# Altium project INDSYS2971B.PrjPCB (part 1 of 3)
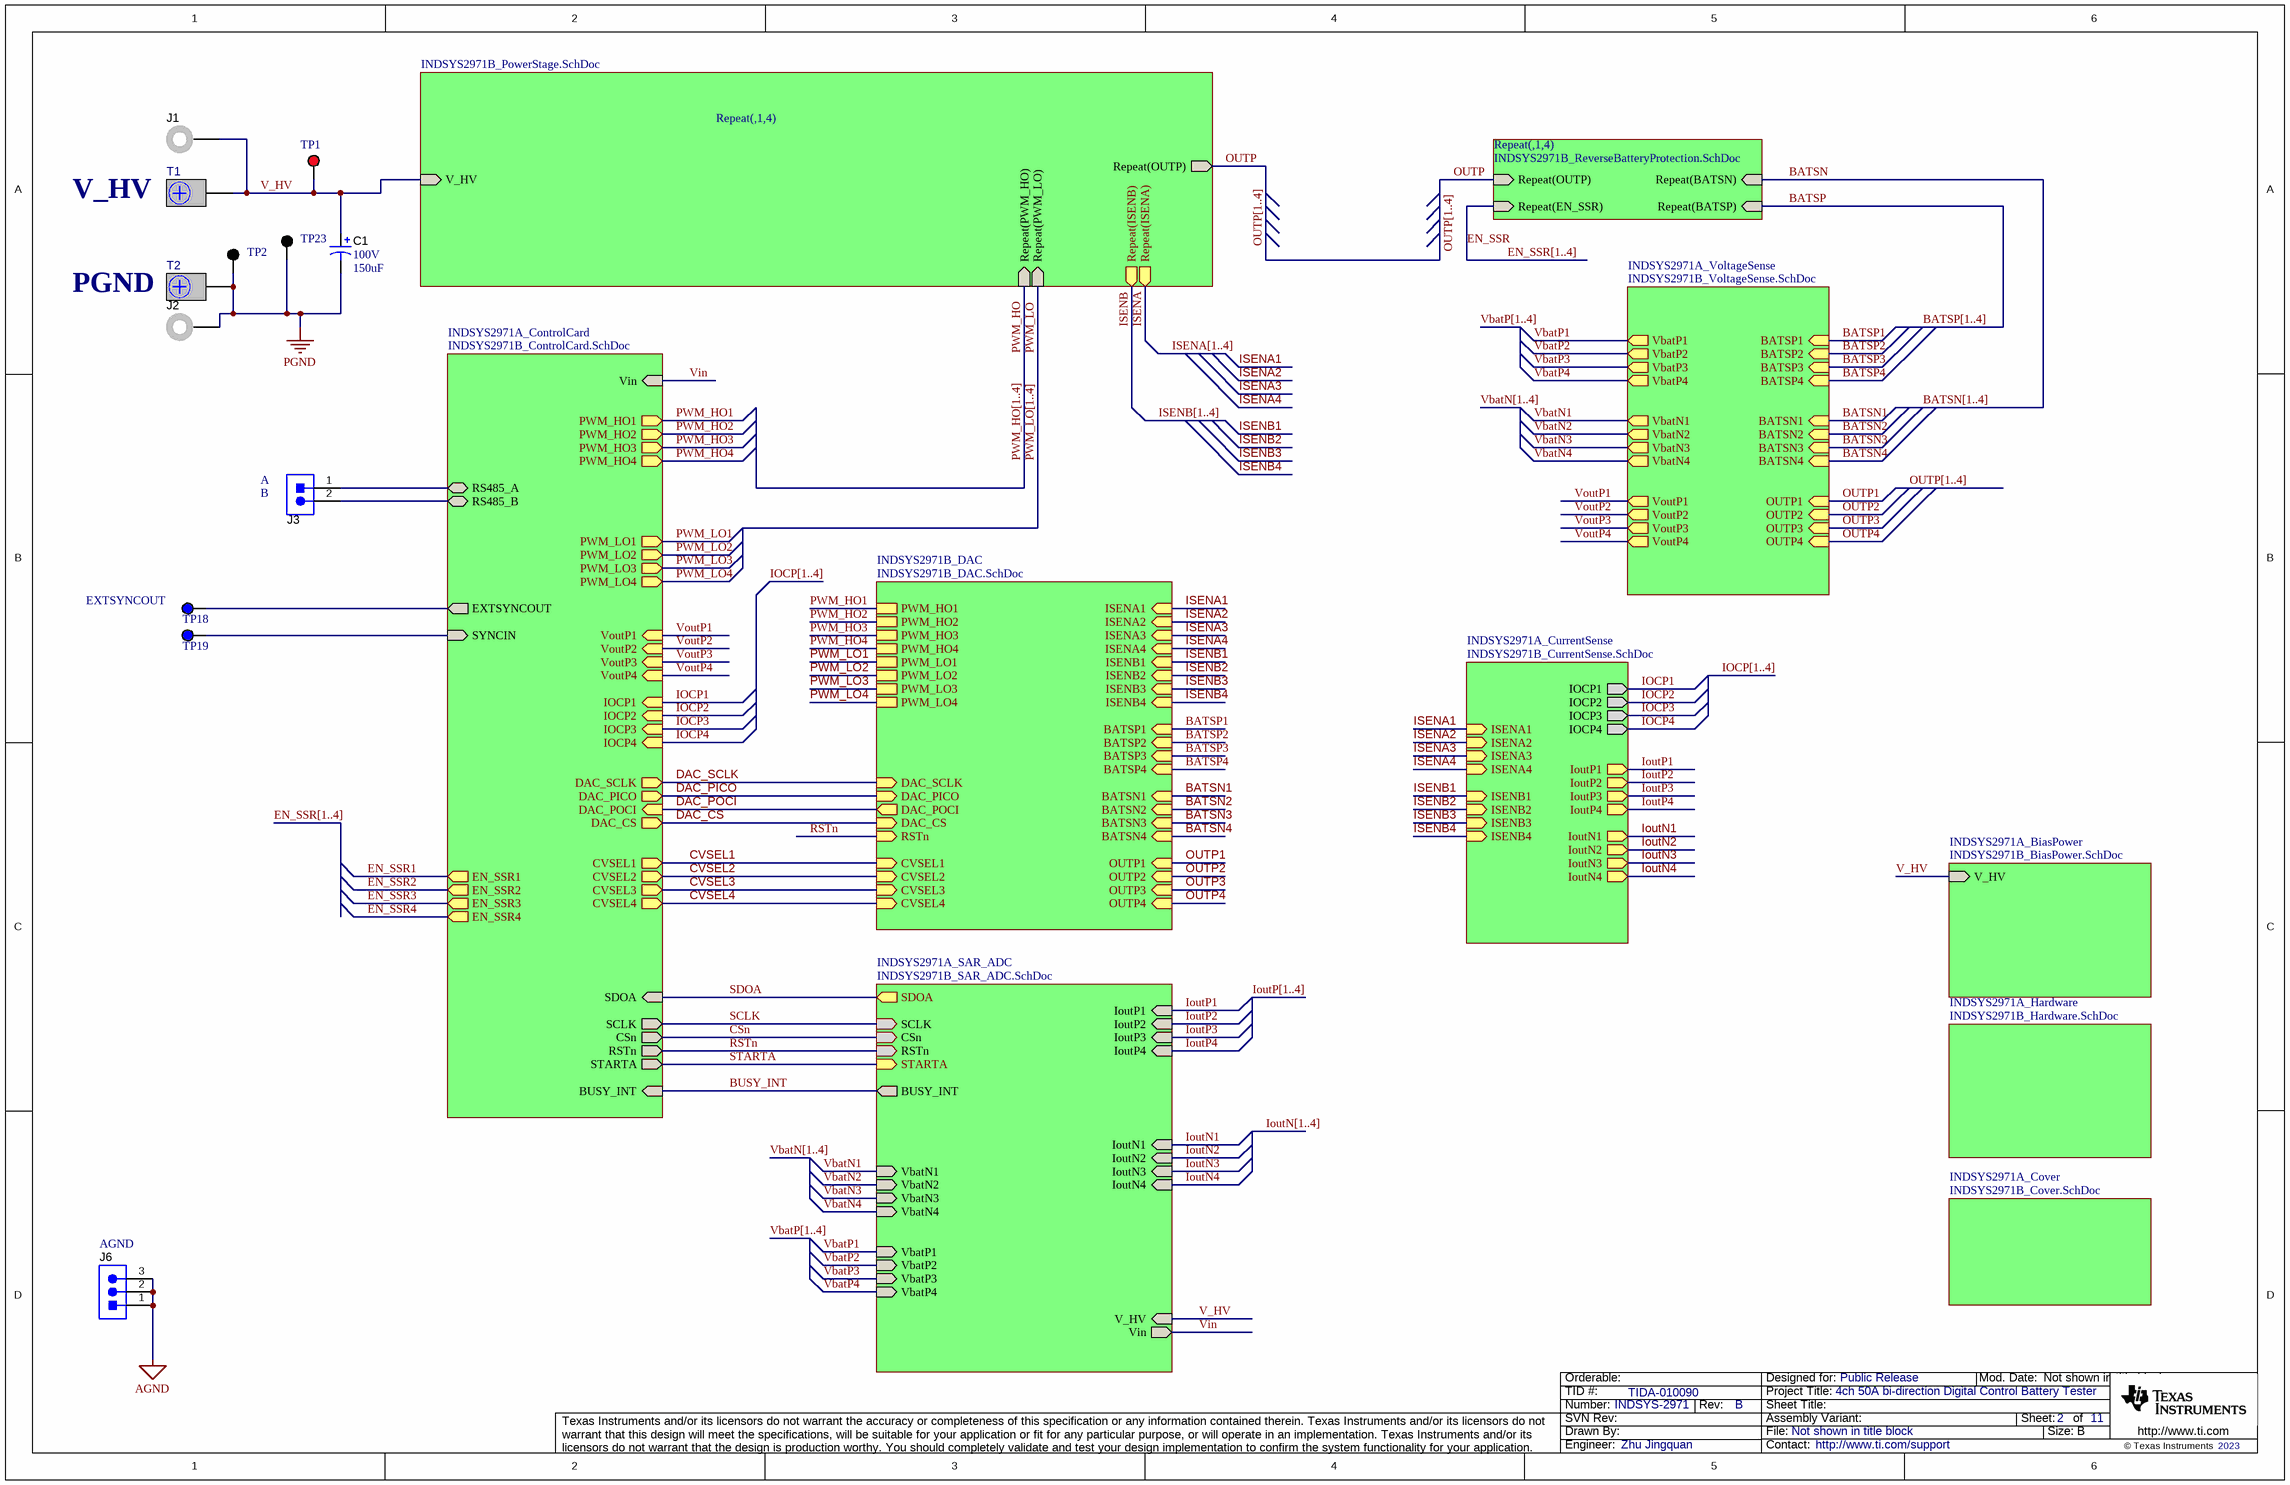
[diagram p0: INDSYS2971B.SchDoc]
CopyrightYear: 2023; PCB_Layout: Zhu Jingquan; PCB_Rev: B; PRJ_Customer: Public Release; PRJ_Engineer: Zhu Jingquan; PRJ_Number: INDSYS-2971; PRJ_Title: 4ch 50A bi-direction Digital Control Battery Tester; SCH_Rev: B; TechSupport: http://www.ti.com/support; TID: TIDA-010090
11 sheets, 788 parts. Net scope: hierarchical (ports join the sheet entries above them; power ports are global).
Board file: INDSYS2971B.PcbDoc
Sheets:
  INDSYS2971B.SchDoc
    1 = INDSYS2971B_PowerStage.SchDoc
    2 = INDSYS2971B_PowerStage.SchDoc
    3 = INDSYS2971B_PowerStage.SchDoc
    4 = INDSYS2971B_PowerStage.SchDoc
    1 = INDSYS2971B_ReverseBatteryProtection.SchDoc
    2 = INDSYS2971B_ReverseBatteryProtection.SchDoc
    3 = INDSYS2971B_ReverseBatteryProtection.SchDoc
    4 = INDSYS2971B_ReverseBatteryProtection.SchDoc
    INDSYS2971A_SAR_ADC = INDSYS2971B_SAR_ADC.SchDoc
    INDSYS2971A_BiasPower = INDSYS2971B_BiasPower.SchDoc
    INDSYS2971A_ControlCard = INDSYS2971B_ControlCard.SchDoc
    INDSYS2971A_Hardware = INDSYS2971B_Hardware.SchDoc
    INDSYS2971A_Cover = INDSYS2971B_Cover.SchDoc
    INDSYS2971A_CurrentSense = INDSYS2971B_CurrentSense.SchDoc
    INDSYS2971A_VoltageSense = INDSYS2971B_VoltageSense.SchDoc
    INDSYS2971B_DAC = INDSYS2971B_DAC.SchDoc

## Sheet INDSYS2971B.SchDoc
size 431 x 279 mm; Date: Not shown in title block; ApprovedBy: Not shown in title block; CheckedBy: Not shown in title block; Author: Not shown in title block; CompanyName: Not shown in title block; Engineer: Not shown in title block; Organization: Not shown in title block; Address1: Not shown in title block; Address2: Not shown in title block; Address3: Not shown in title block; Address4: Not shown in title block; DocumentNumber: 2; Revision: Use project parameter SCH_Rev; SheetNumber: 2; SheetTotal: 11; PageSetup: Record=PageOptions¦CenterHorizontal=True¦CenterVertical=True¦PrintScale=1.00¦XCorrection=1.00¦YCorrection=1.00¦PrintKind=0¦BorderSize=5000000¦LeftOffset=0¦BottomOffset=0¦Orientation=2¦PaperLength=1000¦PaperWidth=1000¦Scale=100¦PaperSource=15¦PrintQuality=600¦MediaType=1¦DitherType=10¦PaperKind=Letter¦PrintScaleMode=1

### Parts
C1  VDC_V: 100V  ValueDisplayed: 150uF  [SM_RADIAL_J16]  (hidden comment: EEV-FK2A151M)
J1  108-0740-001  [Johnson_108-0740-001]  (value not drawn)
J2  108-0740-001  [Johnson_108-0740-001]  (value not drawn)
J3  B2B-EH-A(LF)(SN)  [JST_B2B-EH-A]  (value not drawn)
J6  HTSW-103-07-G-S  [Samtec_HTSW-103-07-G-S]  (value not drawn)
T1  CXS70-14-C  [Panduit_CXS70-14-C]  (value not drawn)
T2  CXS70-14-C  [Panduit_CXS70-14-C]  (value not drawn)
TP1  5000  [Keystone5000]  (value not drawn)
TP2  5001  [Keystone5001]  (value not drawn)
TP18  5117  [Keystone5117]  (value not drawn)
TP19  5117  [Keystone5117]  (value not drawn)
TP23  5001  [Keystone5001]  (value not drawn)

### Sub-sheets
INDSYS2971A_BiasPower = INDSYS2971B_BiasPower.SchDoc: V_HV (in)
INDSYS2971A_ControlCard = INDSYS2971B_ControlCard.SchDoc: SDOA (in), SCLK (out), CSn (out), Vin (in), RSTn (out), EXTSYNCOUT (out), SYNCIN (in), BUSY_INT (in), STARTA (out), RS485_A (bidir), RS485_B (bidir), EN_SSR1 (out), EN_SSR2 (out), EN_SSR3 (out), EN_SSR4 (out), IOCP1 (in), IOCP2 (in), IOCP3 (in), IOCP4 (in), VoutP1 (in), VoutP2 (in), VoutP3 (in), VoutP4 (in), PWM_HO1 (out), PWM_HO2 (out), PWM_HO3 (out), PWM_HO4 (out), PWM_LO1 (out), PWM_LO2 (out), PWM_LO3 (out), PWM_LO4 (out), DAC_SCLK (out), DAC_PICO (out), DAC_POCI (in), DAC_CS (out), CVSEL1 (out), CVSEL2 (out), CVSEL3 (out), CVSEL4 (out)
INDSYS2971A_Cover = INDSYS2971B_Cover.SchDoc: no entries
INDSYS2971A_CurrentSense = INDSYS2971B_CurrentSense.SchDoc: IOCP1 (out), IOCP2 (out), IOCP3 (out), IOCP4 (out), IoutP1 (out), IoutP2 (out), IoutP3 (out), IoutP4 (out), IoutN1 (out), IoutN2 (out), IoutN3 (out), IoutN4 (out), ISENA1 (in), ISENA2 (in), ISENA3 (in), ISENA4 (in), ISENB1 (in), ISENB2 (in), ISENB3 (in), ISENB4 (in)
INDSYS2971A_Hardware = INDSYS2971B_Hardware.SchDoc: no entries
INDSYS2971A_SAR_ADC = INDSYS2971B_SAR_ADC.SchDoc: BUSY_INT (out), IoutP1 (in), IoutP2 (in), VbatP1 (in), IoutN4 (in), IoutN1 (in), VbatN1 (in), IoutP3 (in), IoutP4 (in), IoutN3 (in), IoutN2 (in), VbatN2 (in), VbatN3 (in), VbatN4 (in), VbatP2 (in), VbatP3 (in), VbatP4 (in), V_HV (in), Vin (out), SCLK (in), CSn (in), RSTn (in), SDOA (out), STARTA (in)
INDSYS2971A_VoltageSense = INDSYS2971B_VoltageSense.SchDoc: BATSN1 (in), BATSP1 (in), VoutP1 (out), VbatP1 (out), VbatN1 (out), OUTP1 (in), BATSN2 (in), BATSP2 (in), VbatP2 (out), VbatN2 (out), BATSN3 (in), BATSP3 (in), VbatP3 (out), VbatN3 (out), BATSN4 (in), BATSP4 (in), VbatP4 (out), VbatN4 (out), OUTP2 (in), VoutP2 (out), OUTP3 (in), VoutP3 (out), OUTP4 (in), VoutP4 (out)
INDSYS2971B_DAC = INDSYS2971B_DAC.SchDoc: DAC_SCLK (in), DAC_PICO (in), DAC_POCI (out), DAC_CS (in), CVSEL1 (in), CVSEL2 (in), CVSEL3 (in), CVSEL4 (in), RSTn (in), PWM_HO1, PWM_HO2, PWM_HO3, PWM_HO4, PWM_LO1, PWM_LO2, PWM_LO3, PWM_LO4, BATSP1 (in), BATSP2 (in), BATSP3 (in), BATSP4 (in), BATSN1 (in), BATSN2 (in), BATSN3 (in), BATSN4 (in), OUTP1 (in), OUTP2 (in), OUTP3 (in), OUTP4 (in), ISENA1 (in), ISENA2 (in), ISENA3 (in), ISENA4 (in), ISENB1 (in), ISENB2 (in), ISENB3 (in), ISENB4 (in)
Repeat(,1,4) = INDSYS2971B_PowerStage.SchDoc: V_HV (in), Repeat(OUTP) (out), Repeat(PWM_HO) (in), Repeat(PWM_LO) (in), Repeat(ISENB) (out), Repeat(ISENA) (out)
Repeat(,1,4) = INDSYS2971B_ReverseBatteryProtection.SchDoc: Repeat(BATSN) (in), Repeat(BATSP) (in), Repeat(EN_SSR) (in), Repeat(OUTP) (in)

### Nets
AGND: J6.1 J6.2 J6.3
PGND: C1.2(-) J2.1 T2.1 TP2.1 TP23.1
BATSN1: sheet INDSYS2971A_VoltageSense/BATSN1, sheet INDSYS2971B_DAC/BATSN1
BATSN2: sheet INDSYS2971A_VoltageSense/BATSN2, sheet INDSYS2971B_DAC/BATSN2
BATSN3: sheet INDSYS2971A_VoltageSense/BATSN3, sheet INDSYS2971B_DAC/BATSN3
BATSN4: sheet INDSYS2971A_VoltageSense/BATSN4, sheet INDSYS2971B_DAC/BATSN4
BATSP1: sheet INDSYS2971A_VoltageSense/BATSP1, sheet INDSYS2971B_DAC/BATSP1
BATSP2: sheet INDSYS2971A_VoltageSense/BATSP2, sheet INDSYS2971B_DAC/BATSP2
BATSP3: sheet INDSYS2971A_VoltageSense/BATSP3, sheet INDSYS2971B_DAC/BATSP3
BATSP4: sheet INDSYS2971A_VoltageSense/BATSP4, sheet INDSYS2971B_DAC/BATSP4
BUSY_INT: sheet INDSYS2971A_SAR_ADC/BUSY_INT, sheet INDSYS2971A_ControlCard/BUSY_INT
CSn: sheet INDSYS2971A_SAR_ADC/CSn, sheet INDSYS2971A_ControlCard/CSn
CVSEL1: sheet INDSYS2971A_ControlCard/CVSEL1, sheet INDSYS2971B_DAC/CVSEL1
CVSEL2: sheet INDSYS2971A_ControlCard/CVSEL2, sheet INDSYS2971B_DAC/CVSEL2
CVSEL3: sheet INDSYS2971A_ControlCard/CVSEL3, sheet INDSYS2971B_DAC/CVSEL3
CVSEL4: sheet INDSYS2971A_ControlCard/CVSEL4, sheet INDSYS2971B_DAC/CVSEL4
DAC_CS: sheet INDSYS2971A_ControlCard/DAC_CS, sheet INDSYS2971B_DAC/DAC_CS
DAC_PICO: sheet INDSYS2971A_ControlCard/DAC_PICO, sheet INDSYS2971B_DAC/DAC_PICO
DAC_POCI: sheet INDSYS2971A_ControlCard/DAC_POCI, sheet INDSYS2971B_DAC/DAC_POCI
DAC_SCLK: sheet INDSYS2971A_ControlCard/DAC_SCLK, sheet INDSYS2971B_DAC/DAC_SCLK
IOCP1: sheet INDSYS2971A_ControlCard/IOCP1, sheet INDSYS2971A_CurrentSense/IOCP1
IOCP2: sheet INDSYS2971A_ControlCard/IOCP2, sheet INDSYS2971A_CurrentSense/IOCP2
IOCP3: sheet INDSYS2971A_ControlCard/IOCP3, sheet INDSYS2971A_CurrentSense/IOCP3
IOCP4: sheet INDSYS2971A_ControlCard/IOCP4, sheet INDSYS2971A_CurrentSense/IOCP4
IoutN1: sheet INDSYS2971A_SAR_ADC/IoutN1, sheet INDSYS2971A_CurrentSense/IoutN1
IoutN2: sheet INDSYS2971A_SAR_ADC/IoutN2, sheet INDSYS2971A_CurrentSense/IoutN2
IoutN3: sheet INDSYS2971A_SAR_ADC/IoutN3, sheet INDSYS2971A_CurrentSense/IoutN3
IoutN4: sheet INDSYS2971A_SAR_ADC/IoutN4, sheet INDSYS2971A_CurrentSense/IoutN4
IoutP1: sheet INDSYS2971A_SAR_ADC/IoutP1, sheet INDSYS2971A_CurrentSense/IoutP1
IoutP2: sheet INDSYS2971A_SAR_ADC/IoutP2, sheet INDSYS2971A_CurrentSense/IoutP2
IoutP3: sheet INDSYS2971A_SAR_ADC/IoutP3, sheet INDSYS2971A_CurrentSense/IoutP3
IoutP4: sheet INDSYS2971A_SAR_ADC/IoutP4, sheet INDSYS2971A_CurrentSense/IoutP4
ISENA1: sheet INDSYS2971A_CurrentSense/ISENA1, sheet INDSYS2971B_DAC/ISENA1
ISENA2: sheet INDSYS2971A_CurrentSense/ISENA2, sheet INDSYS2971B_DAC/ISENA2
ISENA3: sheet INDSYS2971A_CurrentSense/ISENA3, sheet INDSYS2971B_DAC/ISENA3
ISENA4: sheet INDSYS2971A_CurrentSense/ISENA4, sheet INDSYS2971B_DAC/ISENA4
ISENB1: sheet INDSYS2971A_CurrentSense/ISENB1, sheet INDSYS2971B_DAC/ISENB1
ISENB2: sheet INDSYS2971A_CurrentSense/ISENB2, sheet INDSYS2971B_DAC/ISENB2
ISENB3: sheet INDSYS2971A_CurrentSense/ISENB3, sheet INDSYS2971B_DAC/ISENB3
ISENB4: sheet INDSYS2971A_CurrentSense/ISENB4, sheet INDSYS2971B_DAC/ISENB4
OUTP: sheet Repeat(,1,4)/Repeat(OUTP), sheet Repeat(,1,4)/Repeat(OUTP)
OUTP1: sheet INDSYS2971A_VoltageSense/OUTP1, sheet INDSYS2971B_DAC/OUTP1
OUTP2: sheet INDSYS2971A_VoltageSense/OUTP2, sheet INDSYS2971B_DAC/OUTP2
OUTP3: sheet INDSYS2971A_VoltageSense/OUTP3, sheet INDSYS2971B_DAC/OUTP3
OUTP4: sheet INDSYS2971A_VoltageSense/OUTP4, sheet INDSYS2971B_DAC/OUTP4
PWM_HO1: sheet INDSYS2971A_ControlCard/PWM_HO1, sheet INDSYS2971B_DAC/PWM_HO1
PWM_HO2: sheet INDSYS2971A_ControlCard/PWM_HO2, sheet INDSYS2971B_DAC/PWM_HO2
PWM_HO3: sheet INDSYS2971A_ControlCard/PWM_HO3, sheet INDSYS2971B_DAC/PWM_HO3
PWM_HO4: sheet INDSYS2971A_ControlCard/PWM_HO4, sheet INDSYS2971B_DAC/PWM_HO4
PWM_LO1: sheet INDSYS2971A_ControlCard/PWM_LO1, sheet INDSYS2971B_DAC/PWM_LO1
PWM_LO2: sheet INDSYS2971A_ControlCard/PWM_LO2, sheet INDSYS2971B_DAC/PWM_LO2
PWM_LO3: sheet INDSYS2971A_ControlCard/PWM_LO3, sheet INDSYS2971B_DAC/PWM_LO3
PWM_LO4: sheet INDSYS2971A_ControlCard/PWM_LO4, sheet INDSYS2971B_DAC/PWM_LO4
RSTn: sheet INDSYS2971A_SAR_ADC/RSTn, sheet INDSYS2971A_ControlCard/RSTn, sheet INDSYS2971B_DAC/RSTn
SCLK: sheet INDSYS2971A_SAR_ADC/SCLK, sheet INDSYS2971A_ControlCard/SCLK
SDOA: sheet INDSYS2971A_SAR_ADC/SDOA, sheet INDSYS2971A_ControlCard/SDOA
STARTA: sheet INDSYS2971A_SAR_ADC/STARTA, sheet INDSYS2971A_ControlCard/STARTA
V_HV: C1.1(+) J1.1 T1.1 TP1.1 ; sheet Repeat(,1,4)/V_HV, sheet INDSYS2971A_SAR_ADC/V_HV, sheet INDSYS2971A_BiasPower/V_HV
VbatN1: sheet INDSYS2971A_SAR_ADC/VbatN1, sheet INDSYS2971A_VoltageSense/VbatN1
VbatN2: sheet INDSYS2971A_SAR_ADC/VbatN2, sheet INDSYS2971A_VoltageSense/VbatN2
VbatN3: sheet INDSYS2971A_SAR_ADC/VbatN3, sheet INDSYS2971A_VoltageSense/VbatN3
VbatN4: sheet INDSYS2971A_SAR_ADC/VbatN4, sheet INDSYS2971A_VoltageSense/VbatN4
VbatP1: sheet INDSYS2971A_SAR_ADC/VbatP1, sheet INDSYS2971A_VoltageSense/VbatP1
VbatP2: sheet INDSYS2971A_SAR_ADC/VbatP2, sheet INDSYS2971A_VoltageSense/VbatP2
VbatP3: sheet INDSYS2971A_SAR_ADC/VbatP3, sheet INDSYS2971A_VoltageSense/VbatP3
VbatP4: sheet INDSYS2971A_SAR_ADC/VbatP4, sheet INDSYS2971A_VoltageSense/VbatP4
Vin: sheet INDSYS2971A_SAR_ADC/Vin, sheet INDSYS2971A_ControlCard/Vin
VoutP1: sheet INDSYS2971A_ControlCard/VoutP1, sheet INDSYS2971A_VoltageSense/VoutP1
VoutP2: sheet INDSYS2971A_ControlCard/VoutP2, sheet INDSYS2971A_VoltageSense/VoutP2
VoutP3: sheet INDSYS2971A_ControlCard/VoutP3, sheet INDSYS2971A_VoltageSense/VoutP3
VoutP4: sheet INDSYS2971A_ControlCard/VoutP4, sheet INDSYS2971A_VoltageSense/VoutP4
NetJ3_1: J3.1 ; sheet INDSYS2971A_ControlCard/RS485_A
NetJ3_2: J3.2 ; sheet INDSYS2971A_ControlCard/RS485_B
NetR54_2: TP19.1 ; sheet INDSYS2971A_ControlCard/SYNCIN
NetR71_2: TP18.1 ; sheet INDSYS2971A_ControlCard/EXTSYNCOUT

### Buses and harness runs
bus BATSN[1..4]
bus BATSP[1..4]
bus EN_SSR[1..4]
bus IOCP[1..4]
bus IoutN[1..4]
bus IoutP[1..4]
bus ISENA[1..4]
bus ISENB[1..4]
bus OUTP[1..4]
bus PWM_HO[1..4]
bus PWM_LO[1..4]
bus VbatN[1..4]
bus VbatP[1..4]

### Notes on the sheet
- V_HV
- PGND
- (near J3) A
- (near J3) B
- EXTSYNCOUT
- (near J6) AGND

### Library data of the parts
C1 = CMP-0011222-2: CAP, AL, 150 uF, 100 V, +/- 20%, 0.17 ohm, AEC-Q200 Grade 2, SMD; Manufacturer: Panasonic; TaMin_C: -55°C; ESR_ohm: 0.17; Polarized: Y; SizeAreaWB_mm2: 399; Value: 150uF; TaMax_C: 105°C; SizeZ_mm: 16.5; SizeX_mm: 19; SizeY_mm: 17; Cap_Case: J16; SizeArea_mm2: 323; CompType: Capacitor; Cap_F: 150µF; IRMS_A: 793mA; AEC Grade: 2; AEC Category: Q200; U/M: EA
J1 J2 = CMP-0055387-2: Standard Banana Jack, Uninsulated, 15A; Manufacturer: Cinch Connectivity; CNHeader: FALSE; Green_Lifecycle: Active; Green_REACh: Passed; CT: TRUE
J3 = CMP-0075228-1: Header (Shrouded), 2.5mm, 2x1, Tin, TH; Manufacturer: JST Manufacturing; Pitch_mm: 2.5; Gender: Male; Shrouded: Y; Row_Count: 1; Current_A: 3A; Voltage_V: 250V; CNHeader: False
J6 = CMP-0075484-1: Header, 100mil, 3x1, Gold, TH; Manufacturer: Samtec; Green_REACh: Passed; CT: False; Green_Lifecycle: Active; CNHeader: True
T1 T2 = CMP-0075010-2: Terminal 70A Lug; Manufacturer: Panduit; CompType: Screw Terminal; CNHeader: False; Green_Lifecycle: Not Set; Green_REACh: Incomplete
TP1 = CMP-0055137-2: Test Point, Miniature, Red, TH; Manufacturer: Keystone Electronics; Green_REACh: Passed; Green_Lifecycle: Active; ContactFinish: Silver; CNHeader: FALSE; CT: TRUE
TP2 TP23 = CMP-0055138-2: Test Point, Miniature, Black, TH; Manufacturer: Keystone Electronics; ContactFinish: Silver; Green_Lifecycle: Active; Green_REACh: Passed; CNHeader: FALSE; CT: TRUE
TP18 TP19 = CMP-0055154-1: Test Point, Miniature, Blue, TH; Manufacturer: Keystone; CNHeader: FALSE; Green_Lifecycle: Active; Green_REACh: Passed; ContactFinish: Silver; CT: TRUE

## Sheet INDSYS2971B_PowerStage.SchDoc
size 431 x 279 mm; Date: Not shown in title block; ApprovedBy: Not shown in title block; CheckedBy: Not shown in title block; Author: Not shown in title block; CompanyName: Not shown in title block; DrawnBy: Battery test; Engineer: Not shown in title block; Organization: Not shown in title block; Address1: Not shown in title block; Address2: Not shown in title block; Address3: Not shown in title block; Address4: Not shown in title block; DocumentNumber: 3; Revision: Use project parameter SCH_Rev; SheetNumber: 3; SheetTotal: 11; PageSetup: Record=PageOptions¦CenterHorizontal=True¦CenterVertical=True¦PrintScale=1.00¦XCorrection=1.00¦YCorrection=1.00¦PrintKind=0¦BorderSize=5000000¦LeftOffset=0¦BottomOffset=0¦Orientation=2¦PaperLength=1000¦PaperWidth=1000¦Scale=100¦PaperSource=15¦PrintQuality=600¦MediaType=1¦DitherType=10¦PaperKind=Letter¦PrintScaleMode=1
Used 4 times, as channels 1, 2, 3, 4. Parts and nets are listed once, with the designators drawn on the sheet.
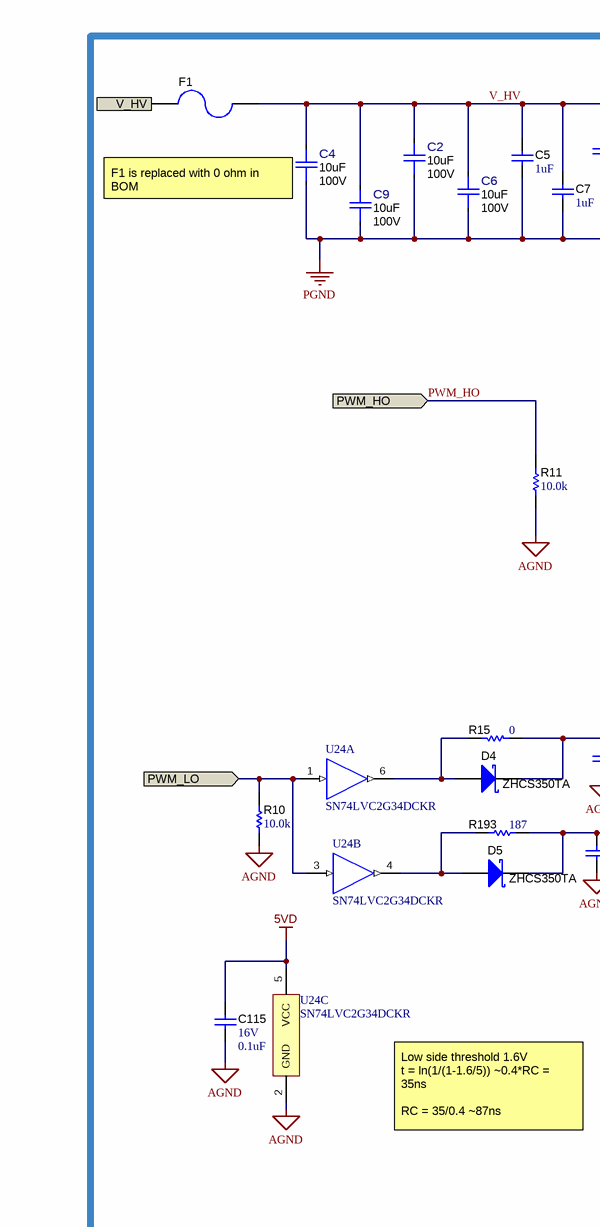
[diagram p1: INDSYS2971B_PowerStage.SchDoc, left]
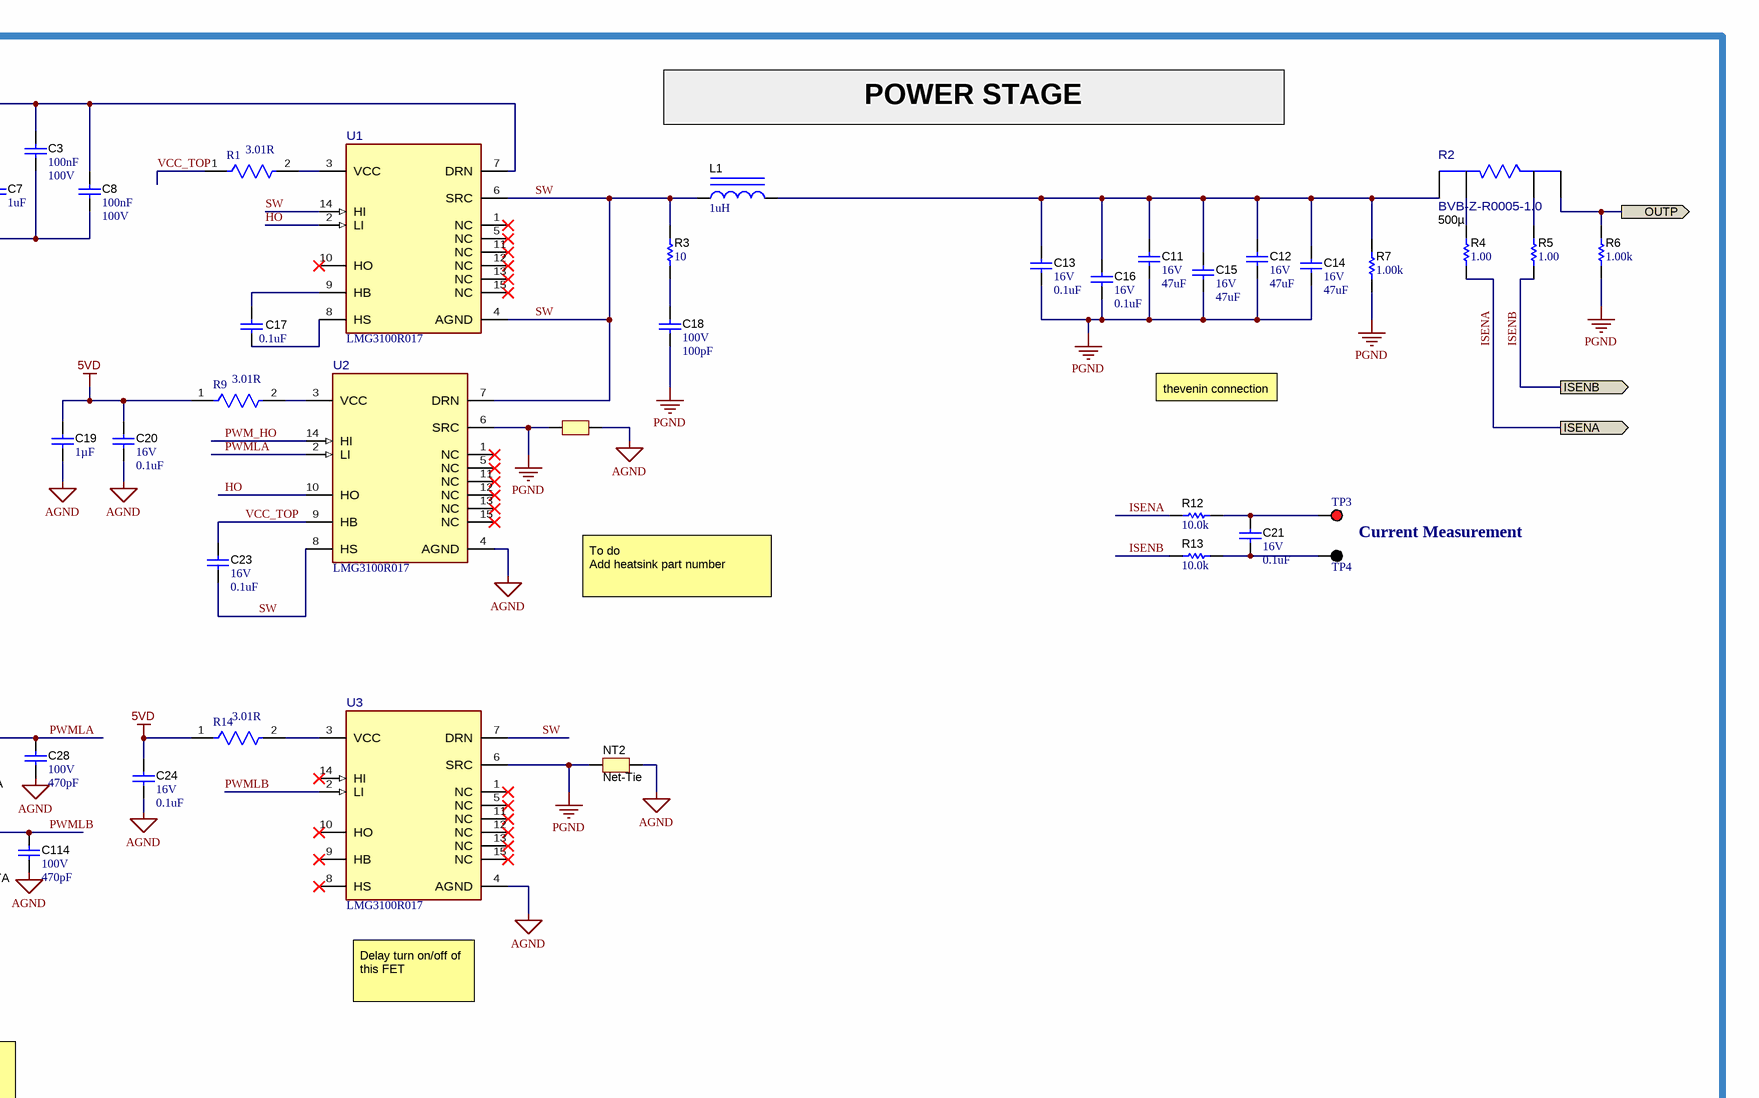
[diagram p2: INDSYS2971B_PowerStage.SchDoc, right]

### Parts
C2  ValueDisplayed: 10uF  VDC_V: 100V  [FP-GRM32EC72A106KE05L_1210-MFG]  (hidden comment: GRM32EC72A106KE05L)
C3  Cap_F: 100nF  VDC_V: 100V  [0603]  (hidden comment: GRM188R72A104KA35D)
C4  ValueDisplayed: 10uF  VDC_V: 100V  [FP-GRM32EC72A106KE05L_1210-MFG]  (hidden comment: GRM32EC72A106KE05L)
C5  ValueDisplayed: 1uF  [0805_HV]  (hidden comment: C2012X7S2A105K125AB)
C6  ValueDisplayed: 10uF  VDC_V: 100V  [FP-GRM32EC72A106KE05L_1210-MFG]  (hidden comment: GRM32EC72A106KE05L)
C7  ValueDisplayed: 1uF  [0805_HV]  (hidden comment: C2012X7S2A105K125AB)
C8  Cap_F: 100nF  VDC_V: 100V  [0603]  (hidden comment: GRM188R72A104KA35D)
C9  ValueDisplayed: 10uF  VDC_V: 100V  [FP-GRM32EC72A106KE05L_1210-MFG]  (hidden comment: GRM32EC72A106KE05L)
C11  VDC_V: 16V  ValueDisplayed: 47uF  [1210_270]  (hidden comment: GRM32EC81C476ME15L)
C12  VDC_V: 16V  ValueDisplayed: 47uF  [1210_270]  (hidden comment: GRM32EC81C476ME15L)
C13  VDC_V: 16V  ValueDisplayed: 0.1uF  [0402]  (hidden comment: GRM155R61C104KA88D)
C14  VDC_V: 16V  ValueDisplayed: 47uF  [1210_270]  (hidden comment: GRM32EC81C476ME15L)
C15  VDC_V: 16V  ValueDisplayed: 47uF  [1210_270]  (hidden comment: GRM32EC81C476ME15L)
C16  VDC_V: 16V  ValueDisplayed: 0.1uF  [0402]  (hidden comment: GRM155R61C104KA88D)
C17  ValueDisplayed: 0.1uF  [0402]  (hidden comment: GRM155R61C104KA88D)
C18  VDC_V: 100V  ValueDisplayed: 100pF  [0805_HV]  (hidden comment: GRM2165C2A101JA01D)
C19  ValueDisplayed: 1µF  [0603S]  (hidden comment: CGA3E1X7R1E105K080AC)
C20  VDC_V: 16V  ValueDisplayed: 0.1uF  [0402]  (hidden comment: GRM155R61C104KA88D)
C21  VDC_V: 16V  ValueDisplayed: 0.1uF  [0402]  (hidden comment: GRM155R61C104KA88D)
C23  VDC_V: 16V  ValueDisplayed: 0.1uF  [0402]  (hidden comment: GRM155R61C104KA88D)
C24  VDC_V: 16V  ValueDisplayed: 0.1uF  [0402]  (hidden comment: GRM155R61C104KA88D)
C28  VDC_V: 100V  ValueDisplayed: 470pF  [0402]  (hidden comment: GRM155R72A471KA01D)
C114  VDC_V: 100V  ValueDisplayed: 470pF  [0402]  (hidden comment: GRM155R72A471KA01D)
C115  VDC_V: 16V  ValueDisplayed: 0.1uF  [0402]  (hidden comment: GRM155R61C104KA88D)
D4  ZHCS350TA  [SOD-523]
D5  ZHCS350TA  [SOD-523]
F1  CB61F15A-TR1  [6125FA]  (value not drawn)
L1  ValueDisplayed: 1uH  [XAL1580]  (hidden comment: XAL1580-102MEB)
NT1  Net-Tie  [Net-Tie_10mil]  (value not drawn)  (net tie, no BOM)
NT2  Net-Tie  [Net-Tie_10mil]  (net tie, no BOM)
R1  Resistance: 3.01R  [FP-CRCW0402-e3-MFG]  (hidden comment: CRCW04023R01FNED)
R2  BVB-Z-R0005-1.0  Res_ohm: 500µ  [FP-WSLP2726L5000FEA_2726-MFG]
R3  ValueDisplayed: 10  [0805_HV]  (hidden comment: CRCW080510R0JNEA)
R4  ValueDisplayed: 1.00  [0402]  (hidden comment: CSR0402FK1R00)
R5  ValueDisplayed: 1.00  [0402]  (hidden comment: CSR0402FK1R00)
R6  ValueDisplayed: 1.00k  [0805_HV]  (hidden comment: CRCW08051K00FKEA)
R7  ValueDisplayed: 1.00k  [0805_HV]  (hidden comment: CRCW08051K00FKEA)
R9  Resistance: 3.01R  [FP-CRCW0402-e3-MFG]  (hidden comment: CRCW04023R01FNED)
R10  ValueDisplayed: 10.0k  [0402]  (hidden comment: PCF0402-12-10K0BT1)
R11  ValueDisplayed: 10.0k  [0402]  (hidden comment: PCF0402-12-10K0BT1)
R12  ValueDisplayed: 10.0k  [0402]  (hidden comment: PCF0402-12-10K0BT1)
R13  ValueDisplayed: 10.0k  [0402]  (hidden comment: PCF0402-12-10K0BT1)
R14  Resistance: 3.01R  [FP-CRCW0402-e3-IPC_C]  (hidden comment: CRCW04023R01FNED)
R15  ValueDisplayed: 0  [0402]  (hidden comment: CRCW04020000Z0ED)
R193  ValueDisplayed: 187  [0402]  (hidden comment: CRCW0402187RFKED)
TP3  5000  [Keystone5000]  (value not drawn)
TP4  5001  [Keystone5001]  (value not drawn)
U1  LMG3100R017  [VBE0015A-MFG]
U2  LMG3100R017  [VBE0015A-MFG]
U3  LMG3100R017  [VBE0015A-MFG]
U24  SN74LVC2G34DCKR  [DCK0006A_N]  (parts A,B,C of 3)

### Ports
ISENA (out), ISENB (out), OUTP (out), PWM_HO (in), PWM_LO (in), V_HV (in)

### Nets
5VD: C19.1 C20.2 C24.2 C115.2 R9.1 R14.1 U24.5(VCC)
AGND: C19.2 C20.1 C24.1 C28.2 C114.2 C115.1 NT1.2 NT2.2 R10.2 R11.2 U2.4(AGND) U3.4(AGND) U24.2(GND)
PGND: C2.1 C3.2 C4.1 C5.2 C6.1 C7.2 C8.2 C9.1 C11.2 C12.2 C13.1 C14.2 C15.2 C16.1 C18.2 NT1.1 NT2.1 R6.1 R7.1 U2.6(SRC) U3.6(SRC)
HO: U1.2(LI) U2.10(HO)
ISENA: R4.1 R12.1 ; port ISENA
ISENB: R5.1 R13.1 ; port ISENB
OUTP: R2.3 R6.2 ; port OUTP
PWM_HO: R11.1 U2.14(HI) ; port PWM_HO
PWM_LO: R10.1 U24.1(1A) U24.3(2A) ; port PWM_LO
PWMLA: C28.1 D4.1(K) R15.2 U2.2(LI)
PWMLB: C114.1 D5.1(K) R193.2 U3.2(LI)
SW: C23.1 L1.1 R3.2 U1.4(AGND) U1.6(SRC) U1.14(HI) U2.7(DRN) U2.8(HS) U3.7(DRN)
V_HV: C2.2 C3.1 C4.2 C5.1 C6.2 C7.1 C8.1 C9.2 F1.1 U1.7(DRN)
V_HV: F1.2 ; port V_HV  [a separate net that carries the same name]
VCC_TOP: C23.2 R1.1 U2.9(HB)
NetC11_1: C11.1 C12.1 C13.2 C14.1 C15.1 C16.2 L1.2 R2.4 R7.2
NetC17_1: C17.1 U1.8(HS)
NetC17_2: C17.2 U1.9(HB)
NetC18_1: C18.1 R3.1
NetC21_1: C21.1 R13.2 TP4.1
NetC21_2: C21.2 R12.2 TP3.1
NetD4_2: D4.2(A) R15.1 U24.6(1Y)
NetD5_2: D5.2(A) R193.1 U24.4(2Y)
NetR1_2: R1.2 U1.3(VCC)
NetR2_1: R2.1 R5.2
NetR2_2: R2.2 R4.2
NetR9_2: R9.2 U2.3(VCC)
NetR14_2: R14.2 U3.3(VCC)

Not connected (* = marked no-connect by the designer): U1 1(NC)* 5(NC)* 10(HO)* 11(NC)* 12(NC)* 13(NC)* 15(NC)*; U2 1(NC)* 5(NC)* 11(NC)* 12(NC)* 13(NC)* 15(NC)*; U3 1(NC)* 5(NC)* 8(HS)* 9(HB)* 10(HO)* 11(NC)* 12(NC)* 13(NC)* 14(HI)* 15(NC)*

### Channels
1: designators end in _1; ports ISENA=ISENA1 ISENB=ISENB1 OUTP=OUTP1 PWM_HO=PWM_HO1 PWM_LO=PWM_LO1 V_HV=V_HV
2: designators end in _2; ports ISENA=ISENA2 ISENB=ISENB2 OUTP=OUTP2 PWM_HO=PWM_HO2 PWM_LO=PWM_LO2 V_HV=V_HV
3: designators end in _3; ports ISENA=ISENA3 ISENB=ISENB3 OUTP=OUTP3 PWM_HO=PWM_HO3 PWM_LO=PWM_LO3 V_HV=V_HV
4: designators end in _4; ports ISENA=ISENA4 ISENB=ISENB4 OUTP=OUTP4 PWM_HO=PWM_HO4 PWM_LO=PWM_LO4 V_HV=V_HV

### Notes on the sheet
- POWER STAGE
- (near C4) F1 is replaced with 0 ohm in BOM
- thevenin connection
- Current Measurement
- To do
  Add heatsink part number
- Delay turn on/off of this FET
- Low side threshold 1.6V
  t = ln(1/(1-1.6/5)) ~0.4*RC = 35ns
  RC = 35/0.4 ~87ns

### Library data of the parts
C2 C4 C6 C9 = CMP-0087970-1: 10µF ±10% 100V Ceramic Capacitor X7S 1210 (3225 Metric); Manufacturer: Murata; Symbol Name: SYM-GRM32EC72A106KE05L; AEC Qualified: No; TempCo: 22%; SizeZ_mm: 2.7mm
C3 C8 = CMP-0007469-4: CAP, CERM, 0.1 uF, 100 V, +/- 10%, X7R, 0603; Manufacturer: MuRata; TaMin_C: -55°C; Polarized: N; SizeAreaWB_mm2: 4.68; Value1: Unknown; U/M: EA; Value: 0.1uF; TaMax_C: 125°C; SizeZ_mm: 1; SizeX_mm: 1.6; SizeY_mm: 0.8; SizeArea_mm2: 1.28; AEC Category: Q200
C5 C7 = CMP-0007891-2: CAP, CERM, 1 uF, 100 V, +/- 10%, X7S, 0805; Manufacturer: TDK; Polarized: N; Value: 1uF; U/M: EA; Cap_F: 1µF; ESR_ohm: 8.255m; Value1: 0.008255 ohm; VDC_V: 100V; IRMS_A: 2.2744A; TaMin_C: -55°C; TaMax_C: 125°C; Cap_Case: 0805; AEC Category: Q200; SizeArea_mm2: 2.5; SizeAreaWB_mm2: 6.75; SizeX_mm: 2; SizeY_mm: 1.25; SizeZ_mm: 1.45
C11 C12 C14 C15 = CMP-0009201-2: CAP, CERM, 47 uF, 16 V, +/- 20%, X6S, 1210; Manufacturer: MuRata; TaMin_C: -55°C; Polarized: N; SizeAreaWB_mm2: 14.7; Value1: Unknown; U/M: EA; Value: 47uF; TaMax_C: 105°C; SizeZ_mm: 2.7; SizeX_mm: 3.2; SizeY_mm: 2.5; Cap_Case: 1210; SizeArea_mm2: 8; Cap_F: 47µF; AEC Category: Q200
C13 C16 C20 C21 C23 C24 C115 = CMP-0006591-2: CAP, CERM, 0.1 uF, 16 V, +/- 10%, X5R, 0402; Manufacturer: MuRata; TaMin_C: -55°C; Polarized: N; SizeAreaWB_mm2: 3; Value1: Unknown; U/M: EA; Value: 0.1uF; TaMax_C: 85°C; SizeZ_mm: 0.6; SizeX_mm: 1; SizeY_mm: 0.5; Cap_F: 100nF; AEC Category: Q200
C17 = CMP-0006591-2: CAP, CERM, 0.1 uF, 16 V, +/- 10%, X5R, 0402; Manufacturer: MuRata; TaMin_C: -55°C; Polarized: N; SizeAreaWB_mm2: 3; Value1: Unknown; U/M: EA; Value: 0.1uF; TaMax_C: 85°C; SizeZ_mm: 0.6; SizeX_mm: 1; SizeY_mm: 0.5; Value2: 16V; Cap_F: 100nF; AEC Category: Q200
C18 = CMP-0008093-2: CAP, CERM, 100 pF, 100 V, +/- 5%, C0G/NP0, 0805; Manufacturer: MuRata; TaMin_C: -55°C; Polarized: N; SizeAreaWB_mm2: 6.75; Value1: Unknown; U/M: EA; Value: 100pF; TaMax_C: 125°C; SizeZ_mm: 1.45; SizeX_mm: 2; SizeY_mm: 1.25; Cap_Case: 0805; SizeArea_mm2: 2.5; AEC Category: Q200
C19 = CMP-0076705-3: CAP, CERM, 1 µF, 25 V,+/- 10%, X7R, AEC-Q200 Grade 1, 0603; Manufacturer: TDK; Polarized: N; Value: 1uF; U/M: EA; VDC_V: 25V; TaMin_C: -55°C; TaMax_C: 125°C; Cap_Case: 1.6x0.8x0.8mm; SizeAreaWB_mm2: 4.68; SizeArea_mm2: 1.28; AEC Qualified: Y; AEC Category: Q200; SizeZ_mm: 1.0; AEC Grade: 1; SizeY_mm: 0.8; SizeX_mm: 1.6
C28 C114 = CMP-0006711-2: CAP, CERM, 470 pF, 100 V, +/- 10%, X7R, 0402; Manufacturer: MuRata; TaMin_C: -55°C; Polarized: N; SizeAreaWB_mm2: 3; Value1: Unknown; U/M: EA; Value: 470pF; TaMax_C: 125°C; SizeZ_mm: 0.6; SizeX_mm: 1; SizeY_mm: 0.5; AEC Category: Q200
D4 D5 = CMP-0028594-3: Diode, Schottky, 40 V, 0.35 A, SOD-523; Manufacturer: Diodes Inc.; SizeY_mm: 0.9; Vf_V: 650mV; Io_A: 350mA; Value2: 0.65V; Green_Lifecycle: Active; AEC Category: Q101; SizeX_mm: 1.7; SizeZ_mm: 0.65; SizeArea_mm2: 1.53; Value1: 0.35A; Green_REACh: Passed; SizeAreaWB_mm2: 5.13; Vr_V: 40V; Value: 40V
F1 = CMP-0003569-2: Fuse, 15 A, SMD; Irating_A: 15A; Rtyp_Ohm: 4m
L1 = CMP-0060973-1: Inductor, Shielded, Composite, 1 uH, 57.5 A, 0.000929 ohm, SMD; Manufacturer: Coilcraft; Isat: 73.5A @ 0.7% inductance drop; Irms: 57.5A @ 40C rise; Green_Lifecycle: Not Set; SizeAreaWB_mm2: 313.04; DCR_ohm: 929µ; Green_REACh: Incomplete; Value: 1uH; Imax_A: 57.5A; SizeZ_mm: 8; SizeX_mm: 15.2; SizeY_mm: 16.2; SizeArea_mm2: 246.24; Ind_H: 1µH; AEC Category: Q200
NT1 NT2 = CMP-0078142-6: Single point connection between nets.
R1 R9 R14 = CMP-02407-004899-1: RES Thick Film, 3.01Ω, 1%, 0.063W, 200ppm/°C, 0402; Max Power Dissipation: 63mW; Voltage Rating (DC): 50V
R2 = CMP-0086415-1: RESISTOR - ISA-WELD SHUNT, 0.000; Manufacturer: Vishay; SizeZ_mm: 3.15mm; Tolerance_%: 1%; Power_W: 9W; TempCo: 75ppm/°C
R3 = CMP-0020448-3: RES, 10, 5%, 0.125 W, AEC-Q200 Grade 0, 0805; Manufacturer: Vishay-Dale; Power_W: 125mW; TempCo: 200 ppm/C; Value_Code: 10R0; Value: 10; EIA_Code: E24; SizeX_mm: 2; SizeY_mm: 1.25; SizeZ_mm: 1.45; Value2: 0.125W; SizeArea_mm2: 2.5; AEC Qualified: Y; VDC_V: 150V; AEC Category: Q200; AEC Grade: 0
R4 R5 = CMP-0081622-1: RES, 1.00, 1%, 0.125 W, 0402; Manufacturer: Stackpole Electronics Inc; Power_W: 125mW; TempCo: 200 ppm/C; Value_Code: 1R00; Value: 1.00; EIA_Code: E96; Res_ohm: 1; SizeY_mm: 0.5; SizeZ_mm: 0.6; Value2: 0.125W; AEC Qualified: N; VDC_V: 200V; AEC Category: Q200; SizeAreaWB_mm2: 3
R6 R7 = CMP-0020951-3: RES, 1.00 k, 1%, 0.125 W, AEC-Q200 Grade 0, 0805; Manufacturer: Vishay-Dale; Power_W: 125mW; TempCo: 100 ppm/C; Value_Code: 1k00; Value: 1.00k; EIA_Code: E96; Res_ohm: 1k; SizeX_mm: 2; SizeY_mm: 1.25; SizeZ_mm: 1.45; Value2: 0.125W; SizeArea_mm2: 2.5; AEC Qualified: Y; VDC_V: 150V; AEC Category: Q200; AEC Grade: 0
R10-R13 = CMP-0026796-1: RES, 10.0 k, 0.1%, 0.063 W, 0402; Manufacturer: TT Electronics/IRC; Power_W: 63mW; TempCo: 10 ppm/C; Value_Code: 10k0; U/M: EA; Value: 10.0k; EIA_Code: E192; Res_ohm: 10k; SizeX_mm: 1; SizeY_mm: 0.5; SizeZ_mm: 0.6; Value2: 0.063W; AEC Qualified: N; VDC_V: 25V; AEC Category: Q200
R15 = CMP-0026822-3: RES, 0, 5%, 0.063 W, AEC-Q200 Grade 0, 0402; Manufacturer: Vishay-Dale; Value: 0; Value_Code: 0000; Power_W: 63mW; Value2: 0.063W; VDC_V: 50V; TempCo: 200 ppm/C; SizeArea_mm2: 0.5; SizeX_mm: 1; SizeZ_mm: 0.6; EIA_Code: E24; AEC Category: Q200; AEC Qualified: Y
R193 = CMP-0026057-3: RES, 187, 1%, 0.063 W, AEC-Q200 Grade 0, 0402; Manufacturer: Vishay-Dale; Power_W: 63mW; TempCo: 100 ppm/C; Value_Code: 187R; Value: 187; EIA_Code: E96; SizeX_mm: 1; SizeY_mm: 0.5; SizeZ_mm: 0.6; Value2: 0.063W; AEC Qualified: Y; VDC_V: 50V; AEC Category: Q200; AEC Grade: 0
TP3 = CMP-0055137-2: as TP1 on sheet INDSYS2971B
TP4 = CMP-0055138-2: as TP2 on sheet INDSYS2971B
U1-U3 = CMP-0037654-1: 100-V, 64-A GaN with Integrated Driver; Manufacturer: Texas Instruments; SizeZ_mm: 0.85mm; AEC Qualified: No; Max Supply Voltage: 5.25V; Min Supply Voltage: 4.75V; Nominal Supply Current: 3mA; Number Of Drivers: 1; Propagation Delay: 55ns; Standoff Height: 0mm; TJmax_C: +125°C
U24 = CMP-0051909-3: Dual Buffer Gate, DCK0006A (SOT-SC70-6); Manufacturer: Texas Instruments; Output Type: CMOS; Bits(#): 2; Input Type: CMOS/TTL; Technology Family: LVC; Schmitt Trigger: No; VCC(Max)(V): 5.5; Rating: Catalog; Output Drive (IOL/IOH)(Max)(mA): 32/-32; ICC @ Nom Voltage(Max)(mA): 0.01; VCC(Min)(V): 1.65; F @ Nom Voltage(Max)(Mhz): 150; Logic: True; Voltage(Nom)(V): 1.8,2.5,3.3,5; tpd @ Nom Voltage(Max)(ns): 8.6,4.4,4.1,3.2; AEC Category: Q200; AEC Qualified: N; CompType: IC; SizeAreaWB_mm2: 9.3; SizeArea_mm2: 4.2; SizeX_mm: 2.1; SizeY_mm: 2.0; SizeZ_mm: 1.1

## Sheet INDSYS2971B_ReverseBatteryProtection.SchDoc
size 431 x 279 mm; Date: Not shown in title block; ApprovedBy: Not shown in title block; CheckedBy: Not shown in title block; Author: Not shown in title block; CompanyName: Not shown in title block; DrawnBy: Battery test; Engineer: Not shown in title block; Organization: Not shown in title block; Address1: Not shown in title block; Address2: Not shown in title block; Address3: Not shown in title block; Address4: Not shown in title block; DocumentNumber: 4; Revision: Use project parameter SCH_Rev; SheetNumber: 4; SheetTotal: 11; PageSetup: Record=PageOptions¦CenterHorizontal=True¦CenterVertical=True¦PrintScale=1.00¦XCorrection=1.00¦YCorrection=1.00¦PrintKind=0¦BorderSize=5000000¦LeftOffset=0¦BottomOffset=0¦Orientation=2¦PaperLength=1000¦PaperWidth=1000¦Scale=100¦PaperSource=15¦PrintQuality=600¦MediaType=1¦DitherType=10¦PaperKind=Letter¦PrintScaleMode=1
Used 4 times, as channels 1, 2, 3, 4. Parts and nets are listed once, with the designators drawn on the sheet.
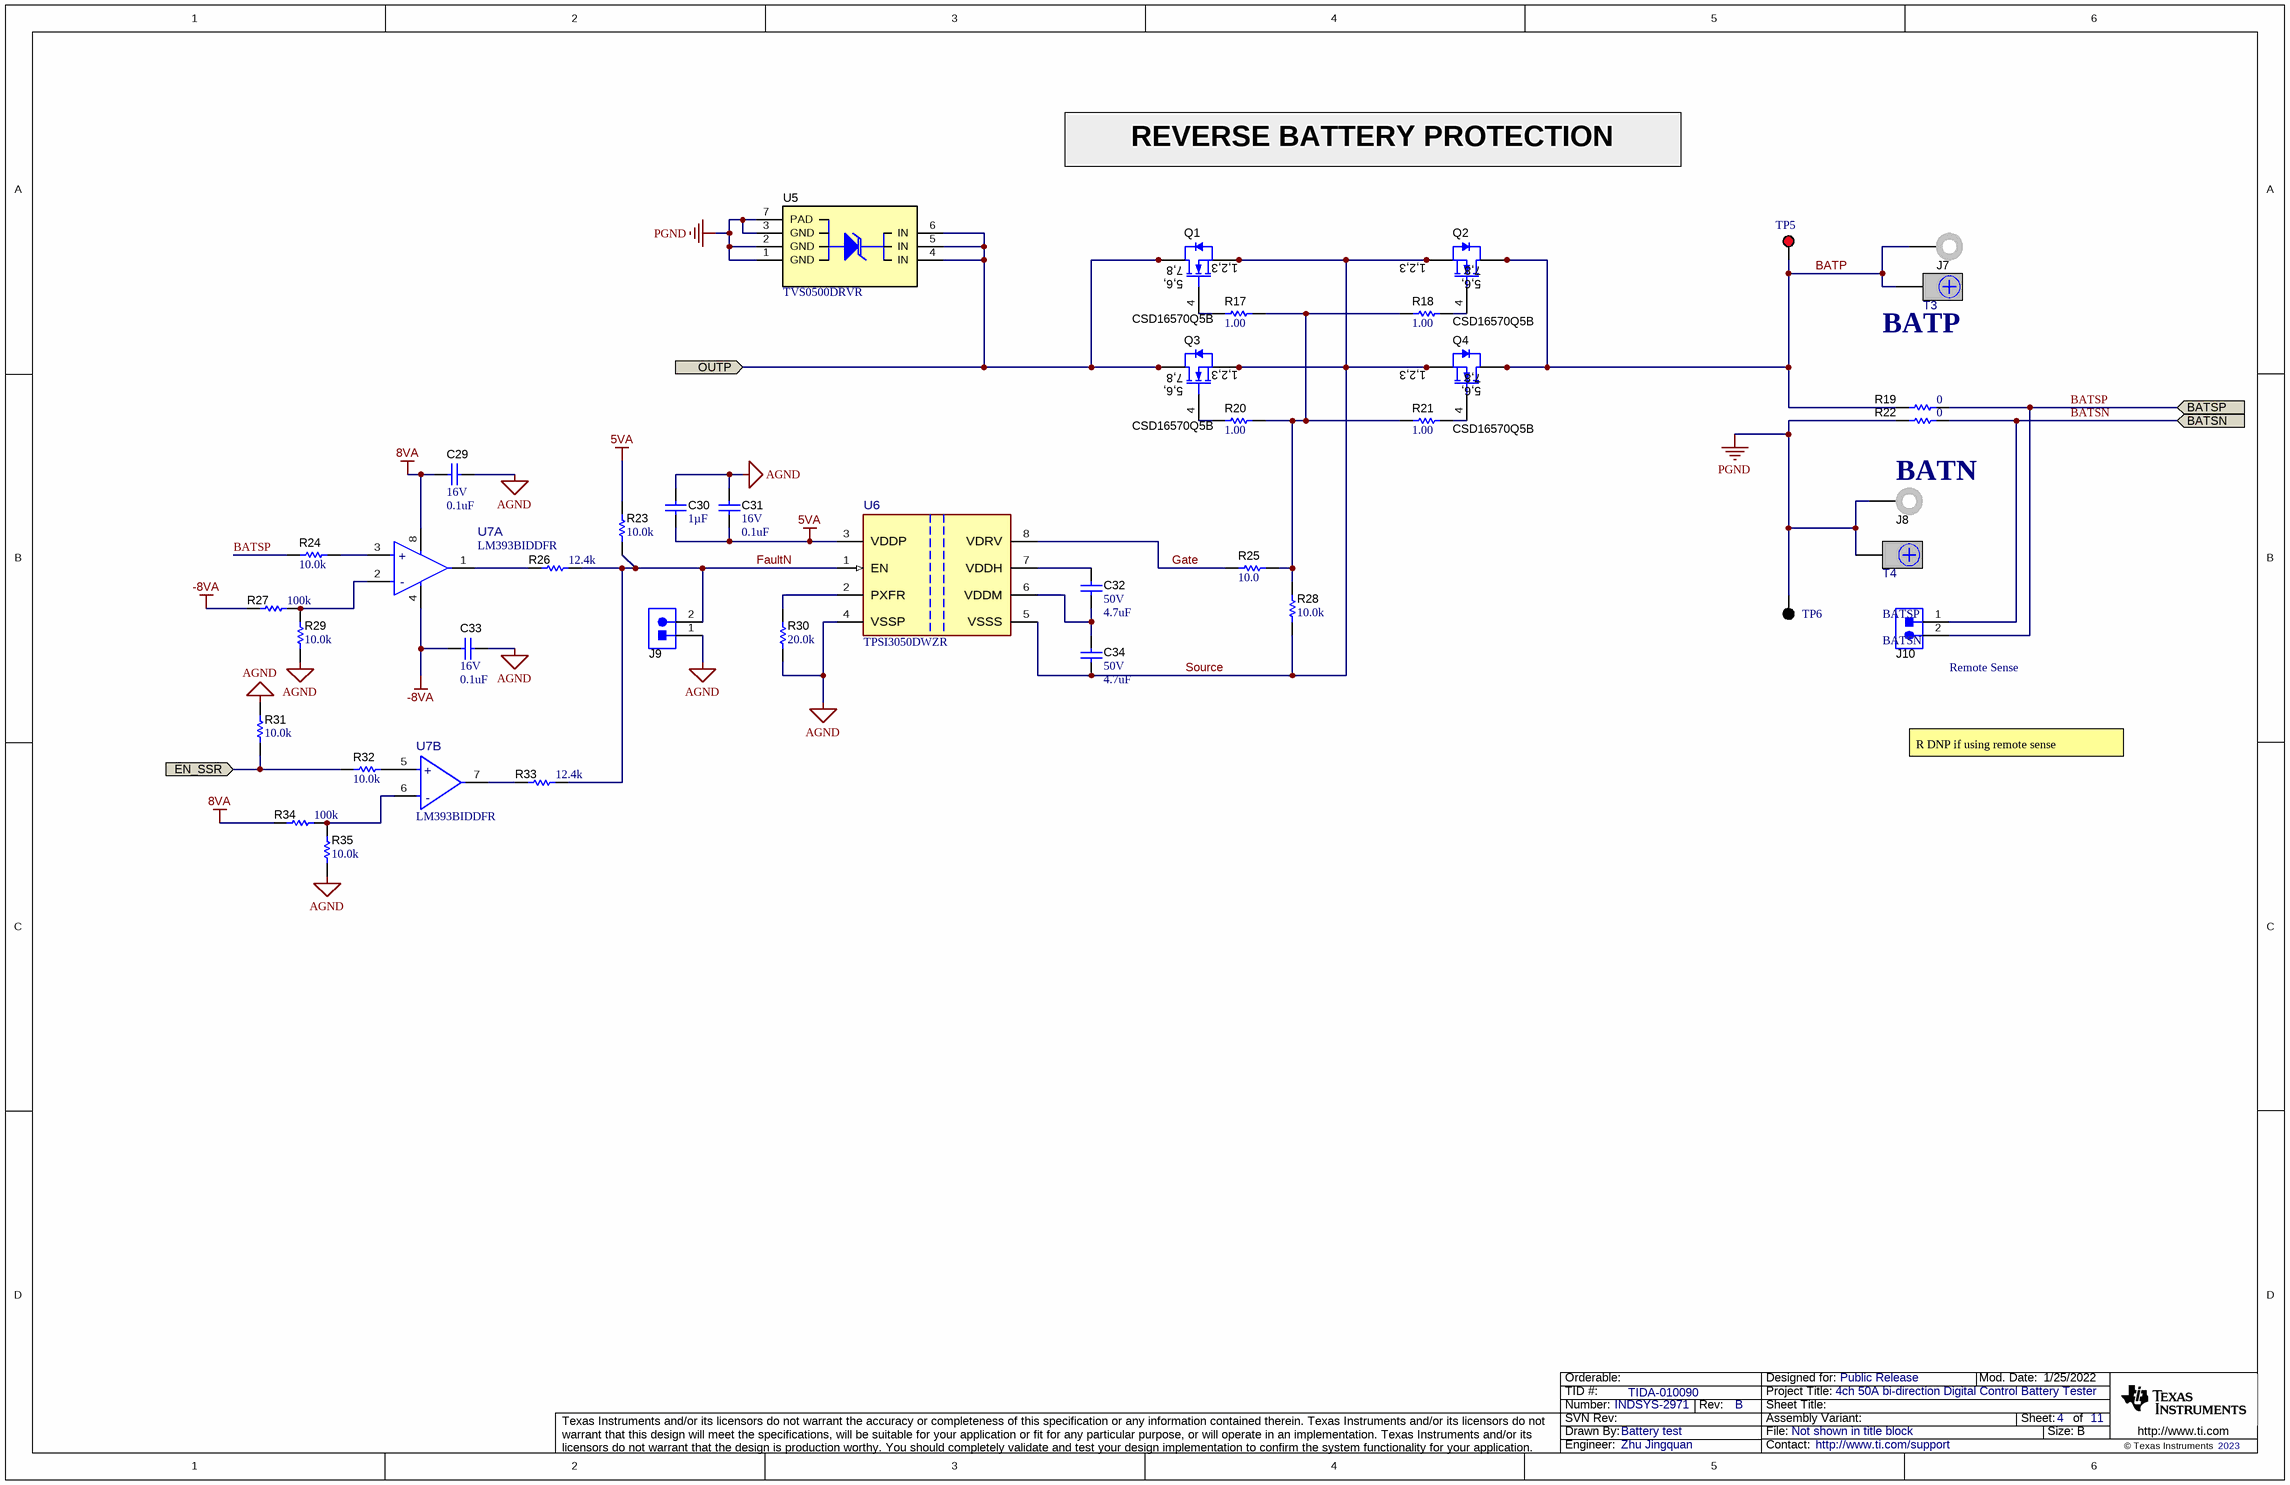
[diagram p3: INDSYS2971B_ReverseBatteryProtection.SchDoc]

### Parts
C29  VDC_V: 16V  ValueDisplayed: 0.1uF  [0402]  (hidden comment: GRM155R61C104KA88D)
C30  ValueDisplayed: 1µF  [0603S]  (hidden comment: CGA3E1X7R1E105K080AC)
C31  VDC_V: 16V  ValueDisplayed: 0.1uF  [0402]  (hidden comment: GRM155R61C104KA88D)
C32  VDC_V: 50V  ValueDisplayed: 4.7uF  [0805_HV]  (hidden comment: GRM21BR61H475KE51L)
C33  VDC_V: 16V  ValueDisplayed: 0.1uF  [0402]  (hidden comment: GRM155R61C104KA88D)
C34  VDC_V: 50V  ValueDisplayed: 4.7uF  [0805_HV]  (hidden comment: GRM21BR61H475KE51L)
J7  108-0740-001  [Johnson_108-0740-001]  (value not drawn)
J8  108-0740-001  [Johnson_108-0740-001]  (value not drawn)
J9  HTSW-102-07-G-S  [Samtec_HTSW-102-07-G-S]  (value not drawn)
J10  B2B-EH-A(LF)(SN)  [JST_B2B-EH-A]  (value not drawn)
Q1  CSD16570Q5B  [DNK0008A]
Q2  CSD16570Q5B  [DNK0008A]
Q3  CSD16570Q5B  [DNK0008A]
Q4  CSD16570Q5B  [DNK0008A]
R17  ValueDisplayed: 1.00  [0402]  (hidden comment: CSR0402FK1R00)
R18  ValueDisplayed: 1.00  [0402]  (hidden comment: CSR0402FK1R00)
R19  ValueDisplayed: 0  [0402]  (hidden comment: CRCW04020000Z0ED)
R20  ValueDisplayed: 1.00  [0402]  (hidden comment: CSR0402FK1R00)
R21  ValueDisplayed: 1.00  [0402]  (hidden comment: CSR0402FK1R00)
R22  ValueDisplayed: 0  [0402]  (hidden comment: CRCW04020000Z0ED)
R23  ValueDisplayed: 10.0k  [0402]  (hidden comment: PCF0402-12-10K0BT1)
R24  ValueDisplayed: 10.0k  [0402]  (hidden comment: PCF0402-12-10K0BT1)
R25  ValueDisplayed: 10.0  [0402]  (hidden comment: CRCW040210R0FKED)
R26  ValueDisplayed: 12.4k  [0402]  (hidden comment: CRCW040212K4FKED)
R27  ValueDisplayed: 100k  [0402]  (hidden comment: RC1005F104CS)
R28  ValueDisplayed: 10.0k  [0402]  (hidden comment: PCF0402-12-10K0BT1)
R29  ValueDisplayed: 10.0k  [0402]  (hidden comment: PCF0402-12-10K0BT1)
R30  ValueDisplayed: 20.0k  [0402]  (hidden comment: CRCW040220K0FKED)
R31  ValueDisplayed: 10.0k  [0402]  (hidden comment: PCF0402-12-10K0BT1)
R32  ValueDisplayed: 10.0k  [0402]  (hidden comment: PCF0402-12-10K0BT1)
R33  ValueDisplayed: 12.4k  [0402]  (hidden comment: CRCW040212K4FKED)
R34  ValueDisplayed: 100k  [0402]  (hidden comment: RC1005F104CS)
R35  ValueDisplayed: 10.0k  [0402]  (hidden comment: PCF0402-12-10K0BT1)
T3  CXS70-14-C  [Panduit_CXS70-14-C]  (value not drawn)
T4  CXS70-14-C  [Panduit_CXS70-14-C]  (value not drawn)
TP5  5000  [Keystone5000]  (value not drawn)
TP6  5001  [Keystone5001]  (value not drawn)
U5  TVS0500DRVR  [DRV0006A]
U6  TPSI3050DWZR  [DWZ0008A-MFG]
U7  LM393BIDDFR  [DDF0008A-MFG]  (parts A,B of 2)

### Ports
BATSN (in), BATSP (in), EN_SSR (in), OUTP (in)

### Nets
5VA: C30.2 C31.2 R23.1 U6.3(VDDP)
8VA: C29.1 R34.1 U7.8(VCC)
-8VA: C33.1 R27.1 U7.4(GND)
AGND: C29.2 C30.1 C31.1 C33.2 J9.1 R29.1 R30.1 R31.2 R35.1 U6.4(VSSP)
PGND: J8.1 R22.1 T4.1 TP6.1 U5.1(GND) U5.2(GND) U5.3(GND) U5.7(PAD)
BATP: J7.1 Q2.5(D) Q2.6(D) Q2.7(D) Q2.8(D) Q2.9(D) Q4.5(D) Q4.6(D) Q4.7(D) Q4.8(D) Q4.9(D) R19.1 T3.1 TP5.1
BATSN: J10.1 R22.2 ; port BATSN
BATSP: J10.2 R19.2 R24.1 ; port BATSP
EN_SSR: R31.1 R32.1 ; port EN_SSR
FaultN: J9.2 R23.2 R26.1 R33.1 U6.1(EN)
Gate: R25.1 U6.8(VDRV)
OUTP: Q1.5(D) Q1.6(D) Q1.7(D) Q1.8(D) Q1.9(D) Q3.5(D) Q3.6(D) Q3.7(D) Q3.8(D) Q3.9(D) U5.4(IN) U5.5(IN) U5.6(IN) ; port OUTP
Source: C34.2 Q1.1(S) Q1.2(S) Q1.3(S) Q2.1(S) Q2.2(S) Q2.3(S) Q3.1(S) Q3.2(S) Q3.3(S) Q4.1(S) Q4.2(S) Q4.3(S) R28.1 U6.5(VSSS)
NetC32_1: C32.1 U6.7(VDDH)
NetC32_2: C32.2 C34.1 U6.6(VDDM)
NetQ1_4: Q1.4(G) R17.2
NetQ2_4: Q2.4(G) R18.1
NetQ3_4: Q3.4(G) R20.2
NetQ4_4: Q4.4(G) R21.1
NetR17_1: R17.1 R18.2 R20.1 R21.2 R25.2 R28.2
NetR24_2: R24.2 U7.3(1IN+)
NetR26_2: R26.2 U7.1(1OUT)
NetR27_2: R27.2 R29.2 U7.2(1IN-)
NetR30_2: R30.2 U6.2(PXFR)
NetR32_2: R32.2 U7.5(2IN+)
NetR33_2: R33.2 U7.7(2OUT)
NetR34_2: R34.2 R35.2 U7.6(2IN-)

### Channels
1: designators end in _1; ports BATSN=BATSN1 BATSP=BATSP1 EN_SSR=EN_SSR1 OUTP=OUTP1
2: designators end in _2; ports BATSN=BATSN2 BATSP=BATSP2 EN_SSR=EN_SSR2 OUTP=OUTP2
3: designators end in _3; ports BATSN=BATSN3 BATSP=BATSP3 EN_SSR=EN_SSR3 OUTP=OUTP3
4: designators end in _4; ports BATSN=BATSN4 BATSP=BATSP4 EN_SSR=EN_SSR4 OUTP=OUTP4

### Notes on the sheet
- REVERSE BATTERY PROTECTION
- (near T3) BATP
- (near J8) BATN
- BATSP
- (near J10) BATSN
- (near J10) Remote Sense
- R DNP if using remote sense

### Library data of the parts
C29 C31 C33 = CMP-0006591-2: as C13 on sheet INDSYS2971B_PowerStage
C30 = CMP-0076705-3: as C19 on sheet INDSYS2971B_PowerStage
C32 C34 = CMP-0008309-2: CAP, CERM, 4.7 uF, 50 V, +/- 10%, X5R, 0805; Manufacturer: MuRata; TaMin_C: -55°C; Polarized: N; SizeAreaWB_mm2: 6.75; Value1: Unknown; U/M: EA; Value: 4.7uF; TaMax_C: 85°C; SizeZ_mm: 1.45; SizeX_mm: 2; SizeY_mm: 1.25; Cap_Case: 0805; SizeArea_mm2: 2.5; Cap_F: 4.7µF; AEC Category: Q200
J7 J8 = CMP-0055387-2: as J1 on sheet INDSYS2971B
J9 = CMP-0075483-1: Header, 100mil, 2x1, Gold, TH; Manufacturer: Samtec; Green_REACh: Passed; CT: False; Green_Lifecycle: Active; CNHeader: True
J10 = CMP-0075228-1: as J3 on sheet INDSYS2971B
Q1-Q4 = CMP-0000274-2: MOSFET, N-CH, 25 V, 100 A, DNK0008A (VSON-CLIP-8); Alternate Manufacturer: None; Manufacturer: Texas Instruments; SizeZ_mm: 1; ChType: N; Value2: 192 nC; VdsMax_V: 25V; SizeX_mm: 6; SizeAreaWB_mm2: 56; SizeY_mm: 5; Vgs_V: 20V; QgTyp_nC: 192; Value: 25V; SizeArea_mm2: 30; AEC Category: Q101; IdsMax_A: 100A; U/M: EA; Rdson45_ohm: 800µ; Value1: 0
R17 R18 R20 R21 = CMP-0081622-1: as R4 on sheet INDSYS2971B_PowerStage
R19 R22 = CMP-0026822-3: as R15 on sheet INDSYS2971B_PowerStage
R23 R24 R29 R31 R32 R35 = CMP-0026796-1: as R10 on sheet INDSYS2971B_PowerStage
R25 = CMP-0025963-3: RES, 10.0, 1%, 0.063 W, AEC-Q200 Grade 0, 0402; Manufacturer: Vishay-Dale; Power_W: 63mW; TempCo: 100 ppm/C; Value_Code: 10R0; Value: 10.0; EIA_Code: E96; Res_ohm: 10; SizeX_mm: 1; SizeY_mm: 0.5; SizeZ_mm: 0.6; Value2: 0.063W; AEC Qualified: Y; VDC_V: 50V; AEC Category: Q200; AEC Grade: 0
R26 R33 = CMP-0025992-3: RES, 12.4 k, 1%, 0.063 W, AEC-Q200 Grade 0, 0402; Manufacturer: Vishay-Dale; Power_W: 63mW; TempCo: 100 ppm/C; Value_Code: 12k4; Value: 12.4k; EIA_Code: E96; SizeX_mm: 1; SizeY_mm: 0.5; SizeZ_mm: 0.6; Value2: 0.063W; AEC Qualified: Y; VDC_V: 50V; AEC Grade: 0; AEC Category: Q200
R27 R34 = CMP-0026745-1: RES, 100 k, 1%, 0.063 W, 0402; Manufacturer: Samsung Electro-Mechanics; Power_W: 63mW; TempCo: 100 ppm/C; U/M: EA; Value: 100k; EIA_Code: E96; SizeX_mm: 1; SizeY_mm: 0.5; SizeZ_mm: 0.6; Value2: 0.063W; AEC Qualified: N; VDC_V: 80V; AEC Category: Q200
R28 = CMP-0026796-1: RES, 10.0 k, 0.1%, 0.063 W, 0402; Manufacturer: TT Electronics/IRC; Power_W: 63mW; TempCo: 10 ppm/C; Value_Code: 10k0; Value: 10.0k; Res_ohm: 10k; SizeX_mm: 1; SizeY_mm: 0.5; SizeZ_mm: 0.6; Value2: 0.063W; AEC Qualified: N; VDC_V: 25V; AEC Category: Q200; EIA_Code: E192; U/M: EA
R30 = CMP-0026162-2: RES, 20.0 k, 1%, 0.063 W, AEC-Q200 Grade 0, 0402; Manufacturer: Vishay-Dale; Power_W: 63mW; TempCo: 100 ppm/C; Value_Code: 20k0; Value: 20.0k; EIA_Code: E96; Res_ohm: 20k; SizeX_mm: 1; SizeY_mm: 0.5; SizeZ_mm: 0.6; Value2: 0.063W; AEC Qualified: Y; VDC_V: 50V; AEC Category: Q200; AEC Grade: 0
T3 T4 = CMP-0075010-2: as T1 on sheet INDSYS2971B
TP5 = CMP-0055137-2: as TP1 on sheet INDSYS2971B
TP6 = CMP-0055138-2: as TP2 on sheet INDSYS2971B
U5 = CMP-0077837-1: 5-V Precision Surge Protection Clamp, DRV0006A (WSON-6); Alternate Manufacturer: Texas Instruments; SizeAreaWB_mm2: 9.0; SizeZ_mm: 0.8; SizeX_mm: 2.0; SizeArea_mm2: 4.0; CompType: IC; AEC Qualified: N; AEC Category: Q200
U6 = CMP-0095182-3: Isolated Switch Driver With Integrated 10-V Gate Supply SOIC8; Manufacturer: Texas Instruments; TaMin_C: -40°C; TJmax_C: +150°C; Nominal Supply Current: 4-33mA; Max Power Dissipation: 350mW; SizeZ_mm: 2.8mm; TaMax_C: +125°C; Min Supply Voltage: 3V; Rise Time: 5ns; Standoff Height: 0.36mm; AEC Qualified: No; Number Of Drivers: 1; Output Voltage: 10V; Max Supply Voltage: 5.5V; AEC Category: Q200; CompType: IC
U7 = CMP-0089113-1: Dual Comparator SOT23-8; Manufacturer: Texas Instruments; Output Current Per Channel: 21mA; TaMin_C: -40°C; Input Bias Current: -0.0035uA; Min Supply Voltage: 3V; Response Time: 1000ns; TJmax_C: +150°C; SizeZ_mm: 1.1mm; Number Of Channels: 2; Max Supply Voltage: 36V; TaMax_C: +85°C; Input Offset Voltage: 0.37mV; Voltage Gain: 200V/mV; Standoff Height: 0mm; AEC Qualified: No; Nominal Supply Current: 400-550uA

## Sheet INDSYS2971B_SAR_ADC.SchDoc
size 431 x 279 mm; Date: Not shown in title block; ApprovedBy: Not shown in title block; CheckedBy: Not shown in title block; Author: Not shown in title block; CompanyName: Not shown in title block; DrawnBy: Battery test; Engineer: Not shown in title block; Organization: Not shown in title block; Address1: Not shown in title block; Address2: Not shown in title block; Address3: Not shown in title block; Address4: Not shown in title block; DocumentNumber: 7; Revision: Use project parameter SCH_Rev; SheetNumber: 7; SheetTotal: 11; PageSetup: Record=PageOptions¦CenterHorizontal=True¦CenterVertical=True¦PrintScale=1.00¦XCorrection=1.00¦YCorrection=1.00¦PrintKind=0¦BorderSize=5000000¦LeftOffset=0¦BottomOffset=0¦Orientation=2¦PaperLength=1000¦PaperWidth=1000¦Scale=100¦PaperSource=15¦PrintQuality=600¦MediaType=1¦DitherType=10¦PaperKind=Letter¦PrintScaleMode=1
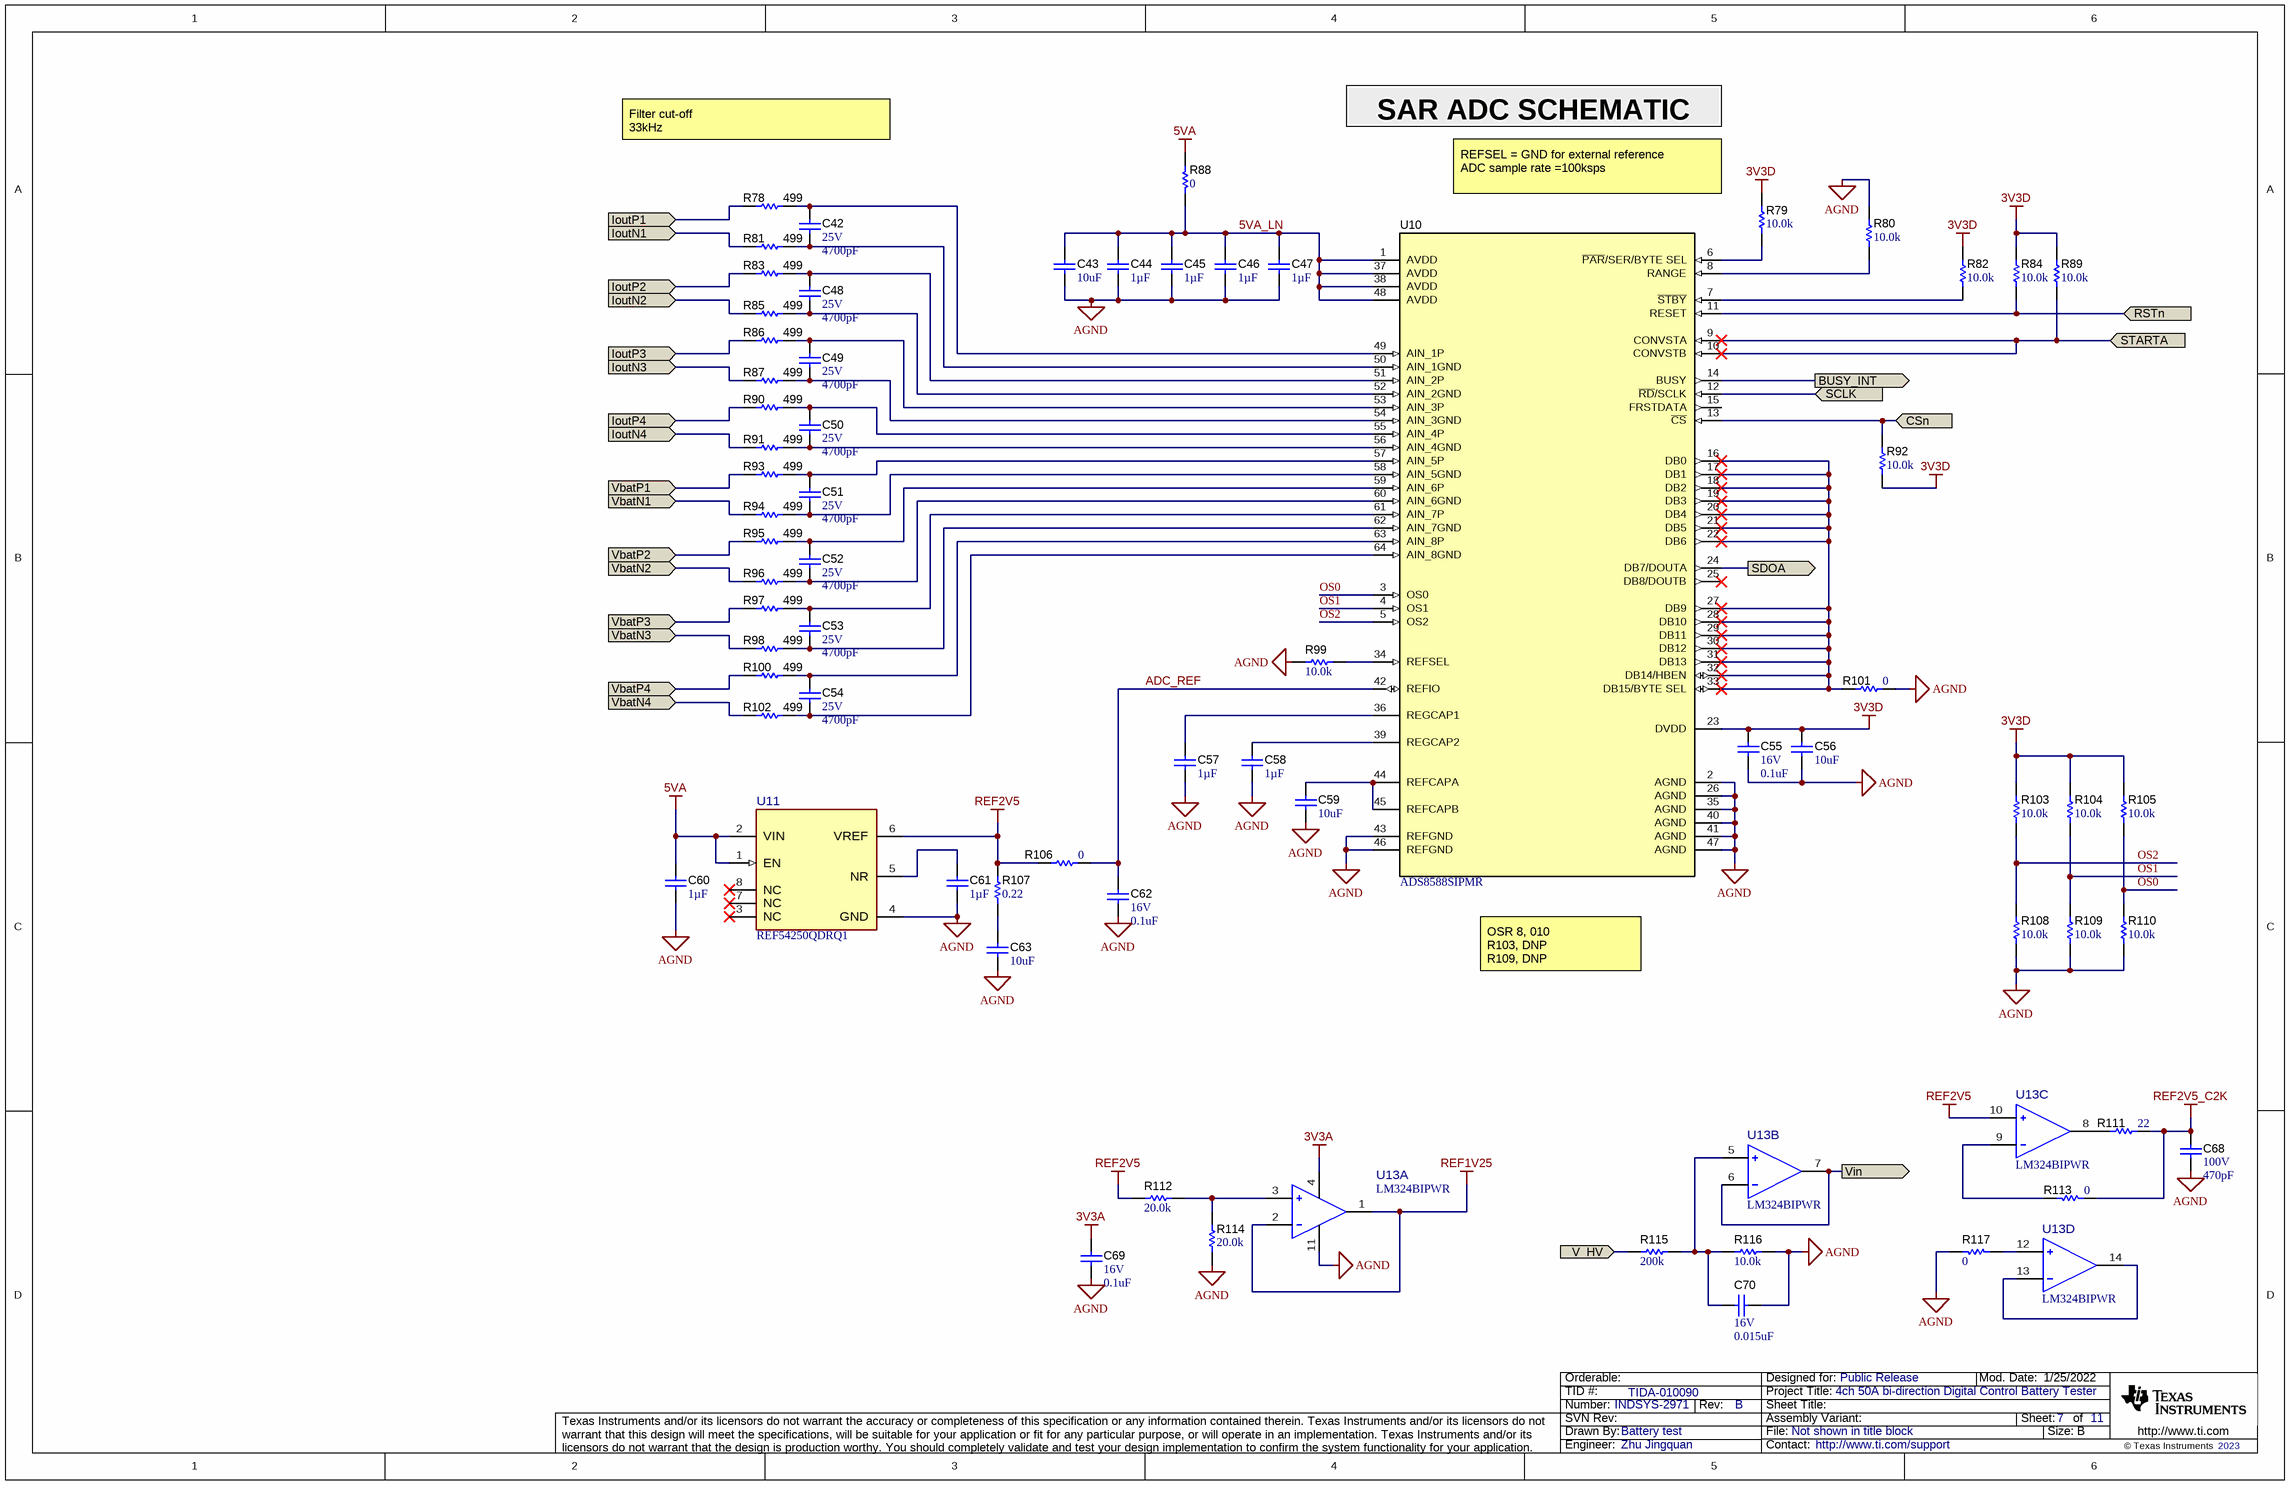
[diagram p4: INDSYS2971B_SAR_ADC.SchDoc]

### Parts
C42  VDC_V: 25V  ValueDisplayed: 4700pF  [0402]  (hidden comment: GRM155R61E472KA01D)
C43  ValueDisplayed: 10uF  [0603]  (hidden comment: GRM188R61E106MA73D)
C44  ValueDisplayed: 1µF  [0603S]  (hidden comment: CGA3E1X7R1E105K080AC)
C45  ValueDisplayed: 1µF  [0603S]  (hidden comment: CGA3E1X7R1E105K080AC)
C46  ValueDisplayed: 1µF  [0603S]  (hidden comment: CGA3E1X7R1E105K080AC)
C47  ValueDisplayed: 1µF  [0603S]  (hidden comment: CGA3E1X7R1E105K080AC)
C48  VDC_V: 25V  ValueDisplayed: 4700pF  [0402]  (hidden comment: GRM155R61E472KA01D)
C49  VDC_V: 25V  ValueDisplayed: 4700pF  [0402]  (hidden comment: GRM155R61E472KA01D)
C50  VDC_V: 25V  ValueDisplayed: 4700pF  [0402]  (hidden comment: GRM155R61E472KA01D)
C51  VDC_V: 25V  ValueDisplayed: 4700pF  [0402]  (hidden comment: GRM155R61E472KA01D)
C52  VDC_V: 25V  ValueDisplayed: 4700pF  [0402]  (hidden comment: GRM155R61E472KA01D)
C53  VDC_V: 25V  ValueDisplayed: 4700pF  [0402]  (hidden comment: GRM155R61E472KA01D)
C54  VDC_V: 25V  ValueDisplayed: 4700pF  [0402]  (hidden comment: GRM155R61E472KA01D)
C55  VDC_V: 16V  ValueDisplayed: 0.1uF  [0402]  (hidden comment: GRM155R61C104KA88D)
C56  ValueDisplayed: 10uF  [0603]  (hidden comment: GRM188R61E106MA73D)
C57  ValueDisplayed: 1µF  [0603S]  (hidden comment: CGA3E1X7R1E105K080AC)
C58  ValueDisplayed: 1µF  [0603S]  (hidden comment: CGA3E1X7R1E105K080AC)
C59  ValueDisplayed: 10uF  [0603]  (hidden comment: GRM188R61E106MA73D)
C60  ValueDisplayed: 1µF  [0603S]  (hidden comment: CGA3E1X7R1E105K080AC)
C61  ValueDisplayed: 1µF  [0603S]  (hidden comment: CGA3E1X7R1E105K080AC)
C62  VDC_V: 16V  ValueDisplayed: 0.1uF  [0402]  (hidden comment: GRM155R61C104KA88D)
C63  ValueDisplayed: 10uF  [0603]  (hidden comment: GRM188R61E106MA73D)
C68  VDC_V: 100V  ValueDisplayed: 470pF  [0402]  (hidden comment: GRM155R72A471KA01D)
C69  VDC_V: 16V  ValueDisplayed: 0.1uF  [0402]  (hidden comment: GRM155R61C104KA88D)
C70  VDC_V: 16V  ValueDisplayed: 0.015uF  [0402]  (hidden comment: GRM155R71C153KA01D)
R78  ValueDisplayed: 499  [0402]  (hidden comment: CRCW0402499RFKED)
R79  ValueDisplayed: 10.0k  [0402]  (hidden comment: PCF0402-12-10K0BT1)
R80  ValueDisplayed: 10.0k  [0402]  (hidden comment: PCF0402-12-10K0BT1)
R81  ValueDisplayed: 499  [0402]  (hidden comment: CRCW0402499RFKED)
R82  ValueDisplayed: 10.0k  [0402]  (hidden comment: PCF0402-12-10K0BT1)
R83  ValueDisplayed: 499  [0402]  (hidden comment: CRCW0402499RFKED)
R84  ValueDisplayed: 10.0k  [0402]  (hidden comment: PCF0402-12-10K0BT1)
R85  ValueDisplayed: 499  [0402]  (hidden comment: CRCW0402499RFKED)
R86  ValueDisplayed: 499  [0402]  (hidden comment: CRCW0402499RFKED)
R87  ValueDisplayed: 499  [0402]  (hidden comment: CRCW0402499RFKED)
R88  ValueDisplayed: 0  [0402]  (hidden comment: CRCW04020000Z0ED)
R89  ValueDisplayed: 10.0k  [0402]  (hidden comment: PCF0402-12-10K0BT1)
R90  ValueDisplayed: 499  [0402]  (hidden comment: CRCW0402499RFKED)
R91  ValueDisplayed: 499  [0402]  (hidden comment: CRCW0402499RFKED)
R92  ValueDisplayed: 10.0k  [0402]  (hidden comment: PCF0402-12-10K0BT1)
R93  ValueDisplayed: 499  [0402]  (hidden comment: CRCW0402499RFKED)
R94  ValueDisplayed: 499  [0402]  (hidden comment: CRCW0402499RFKED)
R95  ValueDisplayed: 499  [0402]  (hidden comment: CRCW0402499RFKED)
R96  ValueDisplayed: 499  [0402]  (hidden comment: CRCW0402499RFKED)
R97  ValueDisplayed: 499  [0402]  (hidden comment: CRCW0402499RFKED)
R98  ValueDisplayed: 499  [0402]  (hidden comment: CRCW0402499RFKED)
R99  ValueDisplayed: 10.0k  [0402]  (hidden comment: PCF0402-12-10K0BT1)
R100  ValueDisplayed: 499  [0402]  (hidden comment: CRCW0402499RFKED)
R101  ValueDisplayed: 0  [0402]  (hidden comment: CRCW04020000Z0ED)
R102  ValueDisplayed: 499  [0402]  (hidden comment: CRCW0402499RFKED)
R103  ValueDisplayed: 10.0k  [0402]  (hidden comment: PCF0402-12-10K0BT1)
R104  ValueDisplayed: 10.0k  [0402]  (hidden comment: PCF0402-12-10K0BT1)
R105  ValueDisplayed: 10.0k  [0402]  (hidden comment: PCF0402-12-10K0BT1)
R106  ValueDisplayed: 0  [0402]  (hidden comment: CRCW04020000Z0ED)
R107  ValueDisplayed: 0.22  [0402]  (hidden comment: ERJ-2BQFR22X)
R108  ValueDisplayed: 10.0k  [0402]  (hidden comment: PCF0402-12-10K0BT1)
R109  ValueDisplayed: 10.0k  [0402]  (hidden comment: PCF0402-12-10K0BT1)
R110  ValueDisplayed: 10.0k  [0402]  (hidden comment: PCF0402-12-10K0BT1)
R111  ValueDisplayed: 22  [0402]  (hidden comment: CRCW040222R0JNED)
R112  ValueDisplayed: 20.0k  [0402]  (hidden comment: CRCW040220K0FKED)
R113  ValueDisplayed: 0  [0402]  (hidden comment: CRCW04020000Z0ED)
R114  ValueDisplayed: 20.0k  [0402]  (hidden comment: CRCW040220K0FKED)
R115  ValueDisplayed: 200k  [0402]  (hidden comment: CRCW0402200KFKED)
R116  ValueDisplayed: 10.0k  [0402]  (hidden comment: PCF0402-12-10K0BT1)
R117  ValueDisplayed: 0  [0402]  (hidden comment: CRCW04020000Z0ED)
U10  ADS8588SIPMR  [PM0064A_L]
U11  REF54250QDRQ1  [D0008A-MFG]
U13  LM324BIPWR  [PW0014A-MFG]  (parts A,B,C,D of 4)

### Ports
BUSY_INT (out), CSn (in), IoutN1 (in), IoutN2 (in), IoutN3 (in), IoutN4 (in), IoutP1 (in), IoutP2 (in), IoutP3 (in), IoutP4 (in), RSTn (in), SCLK (in), SDOA (out), STARTA (in), V_HV (in), VbatN1 (in), VbatN2 (in), VbatN3 (in), VbatN4 (in), VbatP1 (in), VbatP2 (in), VbatP3 (in), VbatP4 (in), Vin (out)

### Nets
3V3A: C69.1 U13.4(VCC+)
3V3D: C55.1 C56.1 R79.2 R82.2 R84.2 R89.2 R92.1 R103.2 R104.2 R105.2 U10.23(DVDD)
5VA: C60.1 R88.1 U11.1(EN) U11.2(VIN)
AGND: C43.2 C44.2 C45.2 C46.2 C47.2 C55.2 C56.2 C57.2 C58.2 C59.2 C60.2 C61.2 C62.2 C63.2 C68.1 C69.2 C70.2 R80.2 R99.1 R101.1 R108.1 R109.1 R110.1 R114.2 R116.2 R117.2 U10.2(AGND) U10.26(AGND) U10.35(AGND) U10.40(AGND) U10.41(AGND) U10.43(REFGND) U10.46(REFGND) U10.47(AGND) U11.4(GND) U13.11(VCC-)
REF1V25: U13.1(1OUT) U13.2(1IN-)
REF2V5: R106.1 R107.2 R112.2 U11.6(VREF) U13.10(3IN+)
REF2V5_C2K: C68.2 R111.2 R113.1
5VA_LN: C43.1 C44.1 C45.1 C46.1 C47.1 R88.2 U10.1(AVDD) U10.37(AVDD) U10.38(AVDD) U10.48(AVDD)
ADC_REF: C62.1 R106.2 U10.42(REFIO)
BUSY_INT: U10.14(BUSY) ; port BUSY_INT
CSn: R92.2 U10.13(~{CS}) ; port CSn
IoutN1: R81.1 ; port IoutN1
IoutN2: R85.1 ; port IoutN2
IoutN3: R87.1 ; port IoutN3
IoutN4: R91.1 ; port IoutN4
IoutP1: R78.1 ; port IoutP1
IoutP2: R83.1 ; port IoutP2
IoutP3: R86.1 ; port IoutP3
IoutP4: R90.1 ; port IoutP4
OS0: R105.1 R110.2 U10.3(OS0)
OS1: R104.1 R109.2 U10.4(OS1)
OS2: R103.1 R108.2 U10.5(OS2)
RSTn: R84.1 U10.11(RESET) ; port RSTn
SCLK: U10.12(~{RD}/SCLK) ; port SCLK
SDOA: U10.24(DB7/DOUTA) ; port SDOA
STARTA: R89.1 U10.9(CONVSTA) U10.10(CONVSTB) ; port STARTA
V_HV: R115.2 ; port V_HV
VbatN1: R94.1 ; port VbatN1
VbatN2: R96.1 ; port VbatN2
VbatN3: R98.1 ; port VbatN3
VbatN4: R102.1 ; port VbatN4
VbatP1: R93.1 ; port VbatP1
VbatP2: R95.1 ; port VbatP2
VbatP3: R97.1 ; port VbatP3
VbatP4: R100.1 ; port VbatP4
Vin: U13.6(2IN-) U13.7(2OUT) ; port Vin
NetC42_1: C42.1 R78.2 U10.49(AIN_1P)
NetC42_2: C42.2 R81.2 U10.50(AIN_1GND)
NetC48_1: C48.1 R83.2 U10.51(AIN_2P)
NetC48_2: C48.2 R85.2 U10.52(AIN_2GND)
NetC49_1: C49.1 R86.2 U10.53(AIN_3P)
NetC49_2: C49.2 R87.2 U10.54(AIN_3GND)
NetC50_1: C50.1 R90.2 U10.55(AIN_4P)
NetC50_2: C50.2 R91.2 U10.56(AIN_4GND)
NetC51_1: C51.1 R93.2 U10.57(AIN_5P)
NetC51_2: C51.2 R94.2 U10.58(AIN_5GND)
NetC52_1: C52.1 R95.2 U10.59(AIN_6P)
NetC52_2: C52.2 R96.2 U10.60(AIN_6GND)
NetC53_1: C53.1 R97.2 U10.61(AIN_7P)
NetC53_2: C53.2 R98.2 U10.62(AIN_7GND)
NetC54_1: C54.1 R100.2 U10.63(AIN_8P)
NetC54_2: C54.2 R102.2 U10.64(AIN_8GND)
NetC57_1: C57.1 U10.36(REGCAP1)
NetC58_1: C58.1 U10.39(REGCAP2)
NetC59_1: C59.1 U10.44(REFCAPA) U10.45(REFCAPB)
NetC61_1: C61.1 U11.5(NR)
NetC63_1: C63.1 R107.1
NetC70_1: C70.1 R115.1 R116.1 U13.5(2IN+)
NetR79_1: R79.1 U10.6(~{PAR}/SER/BYTE_SEL)
NetR80_1: R80.1 U10.8(RANGE)
NetR82_1: R82.1 U10.7(~{STBY})
NetR99_2: R99.2 U10.34(REFSEL)
NetR101_2: R101.2 U10.16(DB0) U10.17(DB1) U10.18(DB2) U10.19(DB3) U10.20(DB4) U10.21(DB5) U10.22(DB6) U10.27(DB9) U10.28(DB10) U10.29(DB11) U10.30(DB12) U10.31(DB13) U10.32(DB14/HBEN) U10.33(DB15/BYTE_SEL)
NetR111_1: R111.1 U13.8(3OUT)
NetR112_1: R112.1 R114.1 U13.3(1IN+)
NetR113_2: R113.2 U13.9(3IN-)
NetR117_1: R117.1 U13.12(4IN+)
NetU13_13: U13.13(4IN-) U13.14(4OUT)

Not connected (* = marked no-connect by the designer): U10 15(FRSTDATA) 25(DB8/DOUTB)*; U11 3(NC)* 7(NC)* 8(NC)*

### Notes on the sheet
- Filter cut-off
  33kHz
- SAR ADC SCHEMATIC
- REFSEL = GND for external reference
  ADC sample rate =100ksps
- OSR 8, 010
  R103, DNP
  R109, DNP
  R105, DNP

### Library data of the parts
C42 C48-C54 = CMP-0006611-2: CAP, CERM, 4700 pF, 25 V, +/- 10%, X5R, 0402; Manufacturer: MuRata; TaMin_C: -55°C; Polarized: N; SizeAreaWB_mm2: 3; Value1: Unknown; U/M: EA; Value: 4700pF; TaMax_C: 85°C; SizeZ_mm: 0.6; SizeX_mm: 1; SizeY_mm: 0.5; Cap_F: 4.7nF; AEC Category: Q200
C43 C56 C59 C63 = CMP-0007344-5: CAP, CERM, 10 uF, 25 V, +/- 20%, X5R, 0603; Manufacturer: MuRata; Polarized: N; Value: 10uF; U/M: EA; Cap_F: 10µF; Value1: Unknown; VDC_V: 25V; TaMin_C: -55°C; TaMax_C: 85°C; SizeArea_mm2: 1.28; SizeAreaWB_mm2: 4.68; SizeX_mm: 1.6; SizeY_mm: 0.8; SizeZ_mm: 1; AEC Category: Q200
C44-C47 C57 C58 C60 C61 = CMP-0076705-3: as C19 on sheet INDSYS2971B_PowerStage
C55 C62 C69 = CMP-0006591-2: as C13 on sheet INDSYS2971B_PowerStage
C68 = CMP-0006711-2: as C28 on sheet INDSYS2971B_PowerStage
C70 = CMP-0006644-2: CAP, CERM, 0.015 uF, 16 V, +/- 10%, X7R, 0402; Manufacturer: MuRata; TaMin_C: -55°C; Polarized: N; SizeAreaWB_mm2: 3; Value1: Unknown; U/M: EA; TaMax_C: 125°C; SizeZ_mm: 0.6; SizeX_mm: 1; SizeY_mm: 0.5; Cap_F: 15nF; AEC Category: Q200
R78 R81 R83 R85-R87 R90 R91 R93-R98 R100 R102 = CMP-0026402-2: RES, 499, 1%, 0.063 W, AEC-Q200 Grade 0, 0402; Manufacturer: Vishay-Dale; Power_W: 63mW; TempCo: 100 ppm/C; Value_Code: 499R; Value: 499; EIA_Code: E96; SizeX_mm: 1; SizeY_mm: 0.5; SizeZ_mm: 0.6; Value2: 0.063W; AEC Qualified: Y; VDC_V: 50V; AEC Category: Q200; AEC Grade: 0
R79 R80 R82 R84 R89 R92 R99 R103-R105 R108-R110 R116 = CMP-0026796-1: as R10 on sheet INDSYS2971B_PowerStage
R88 R101 R106 R113 R117 = CMP-0026822-3: as R15 on sheet INDSYS2971B_PowerStage
R107 = CMP-0026632-2: RES, 0.22, 1%, 0.125 W, AEC-Q200 Grade 0, 0402; Manufacturer: Panasonic; Power_W: 125mW; TempCo: 250 ppm/C; Value_Code: R220; Value: 0.22; EIA_Code: E96; SizeX_mm: 1; SizeY_mm: 0.5; SizeZ_mm: 0.6; Value2: 0.125W; AEC Qualified: Y; AEC Category: Q200; AEC Grade: 0; SizeAreaWB_mm2: 3
R111 = CMP-0026880-3: RES, 22, 5%, 0.063 W, AEC-Q200 Grade 0, 0402; Manufacturer: Vishay-Dale; Power_W: 63mW; TempCo: 200 ppm/C; Value_Code: 22R0; Value: 22; EIA_Code: E24; SizeX_mm: 1; SizeY_mm: 0.5; SizeZ_mm: 0.6; Value2: 0.063W; AEC Qualified: Y; VDC_V: 50V; AEC Category: Q200; AEC Grade: 0
R112 R114 = CMP-0026162-2: as R30 on sheet INDSYS2971B_ReverseBatteryProtection
R115 = CMP-0026158-2: RES, 200 k, 1%, 0.063 W, AEC-Q200 Grade 0, 0402; Manufacturer: Vishay-Dale; Power_W: 63mW; TempCo: 100 ppm/C; Value: 200k; EIA_Code: E96; SizeX_mm: 1; SizeY_mm: 0.5; SizeZ_mm: 0.6; Value2: 0.063W; AEC Qualified: Y; VDC_V: 50V; AEC Category: Q200; AEC Grade: 0
U10 = CMP-0075962-3: 16-Bit High-Speed 8-Channel Simultaneous-Sampling ADC With Bipolar Inputs on a Single Supply, PM0064A (LQFP-64); Manufacturer: Texas Instruments; SizeZ_mm: 1.6; SizeX_mm: 12.0; SizeArea_mm2: 144.0; CompType: IC; SizeAreaWB_mm2: 196.0; AEC Category: Q200; AEC Qualified: N; Rating: Catalog
U11 = CMP-0095913-1: 0.5 ppm/°C Maximum Drift, 0.1 ppmp-p 1/f Noise, 350 μA current, Precision Voltage Reference; Manufacturer: Texas Instruments; Number Of Outputs: 1; SizeZ_mm: 1.75mm; Standoff Height: 0.11mm; AEC Qualified: Yes; Reference Type: Series
U13 = CMP-0120501-1: Quad, 36-V, 1.2-MHz 3-mV offset voltage operational amplifier; Manufacturer: Texas Instruments; SizeZ_mm: 1.2mm; AEC Qualified: No; Gain Bandwidth: 1.2MHz; Input Bias Current: -0.01uA; Input Offset Voltage: 0.6mV; Max Dual Supply Voltage: 18V; Max Supply Voltage: 36V; Min Dual Supply Voltage: 2.5V; Min Supply Voltage: 5V; Nominal Supply Current: 240-350uA; Number Of Channels: 4; Output Current Per Channel: 20mA; Response Time: 4us; Standoff Height: 0.05mm; TaMax_C: +85°C; TaMin_C: -40°C; TJmax_C: +150°C; Voltage Gain: 100V/mV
